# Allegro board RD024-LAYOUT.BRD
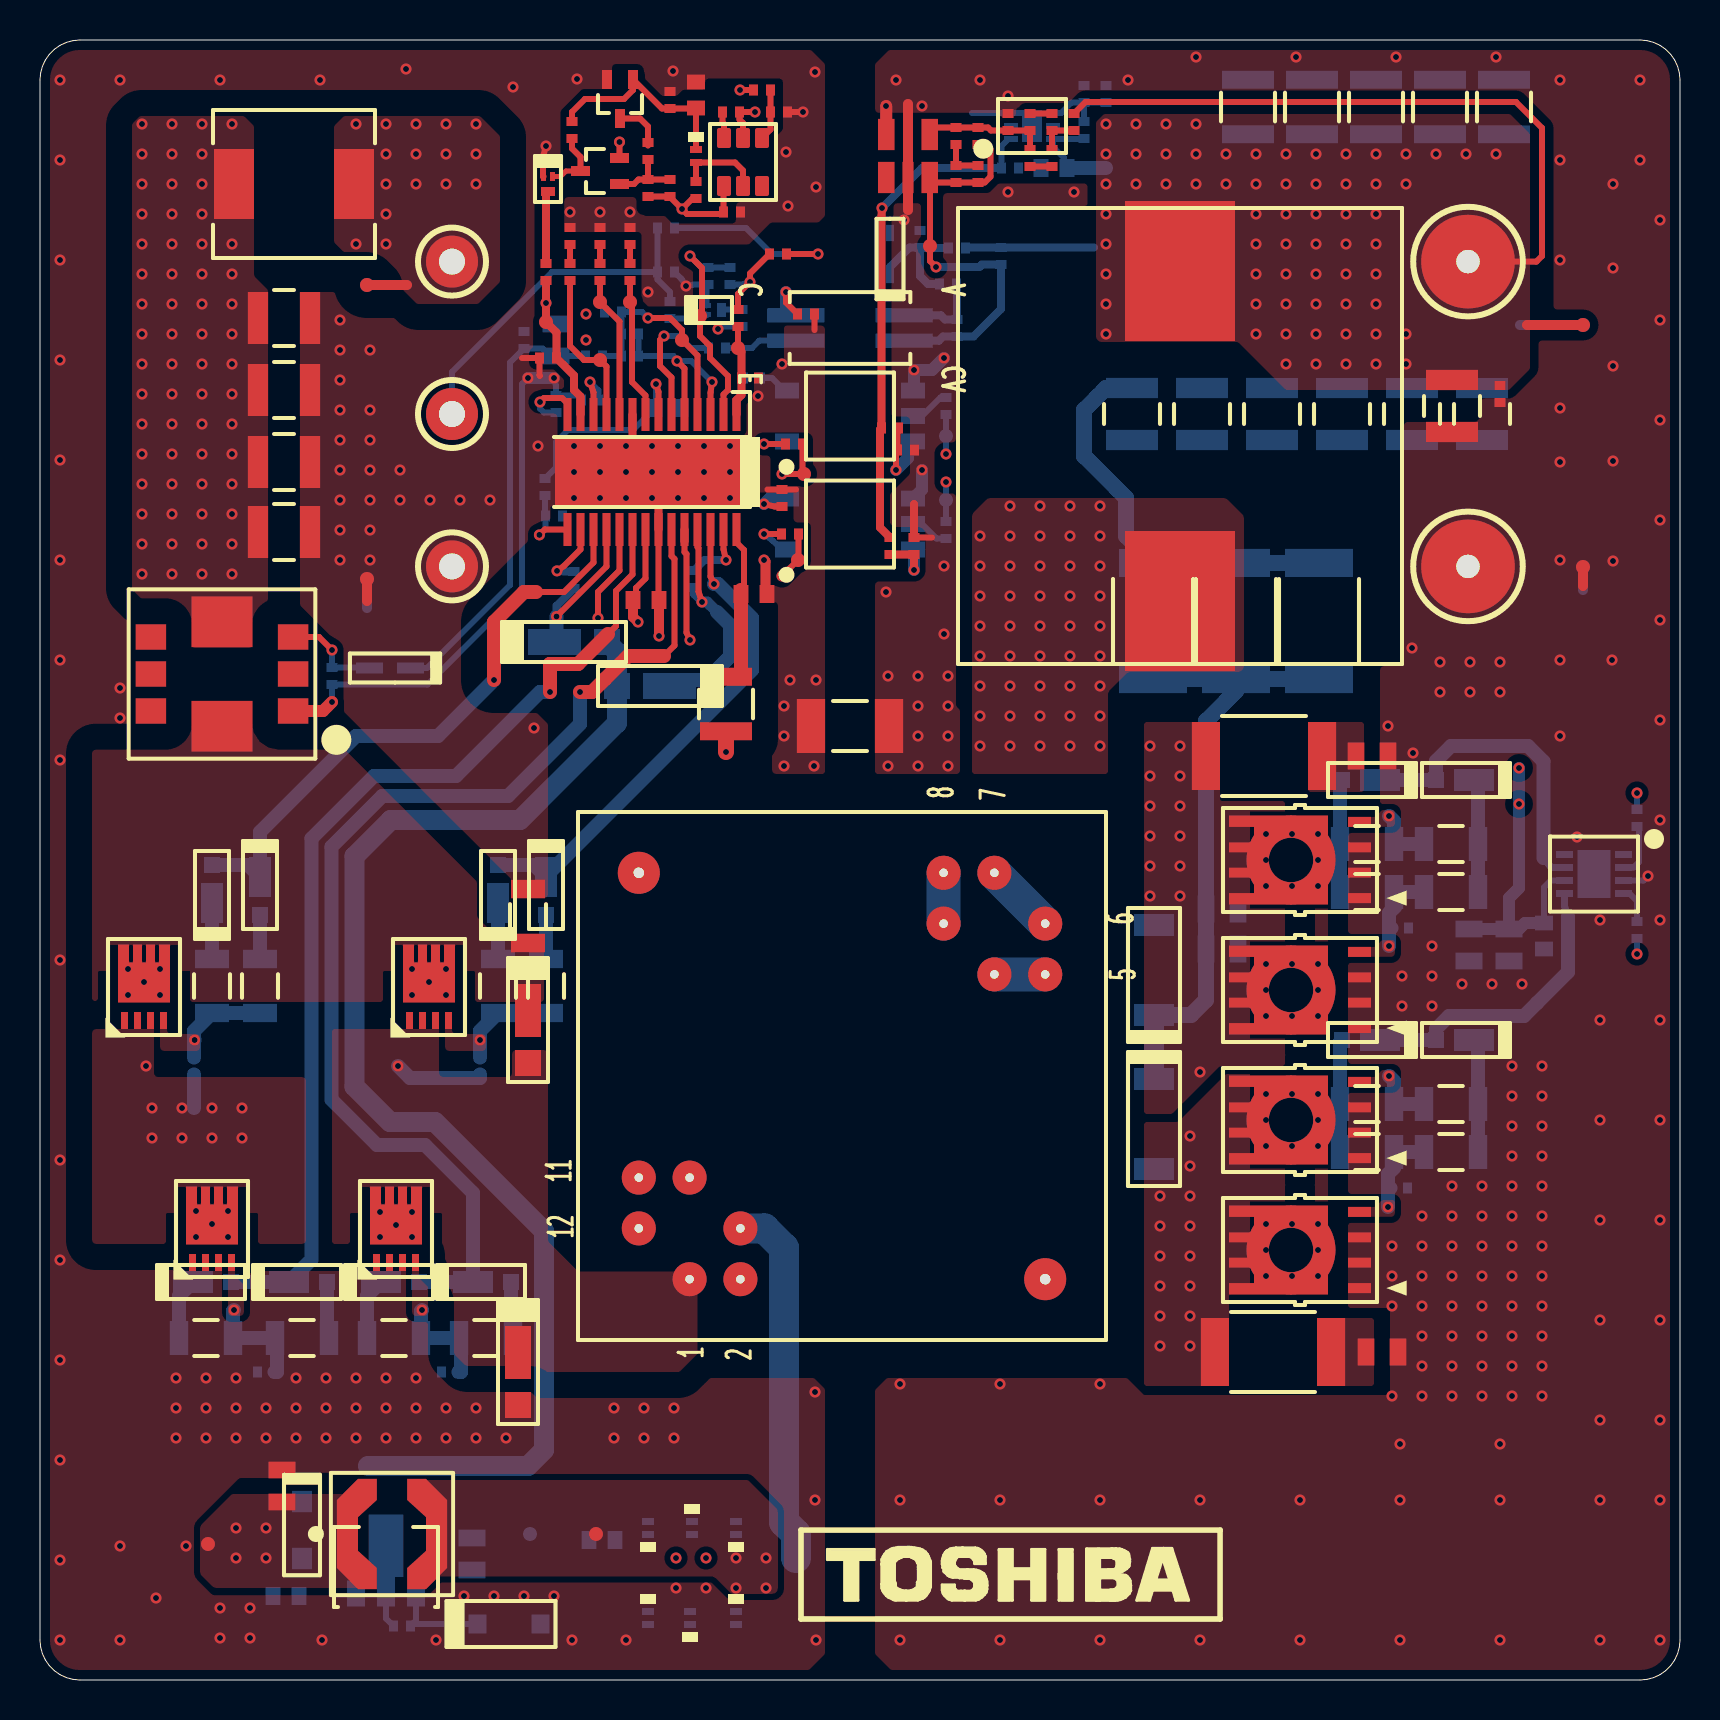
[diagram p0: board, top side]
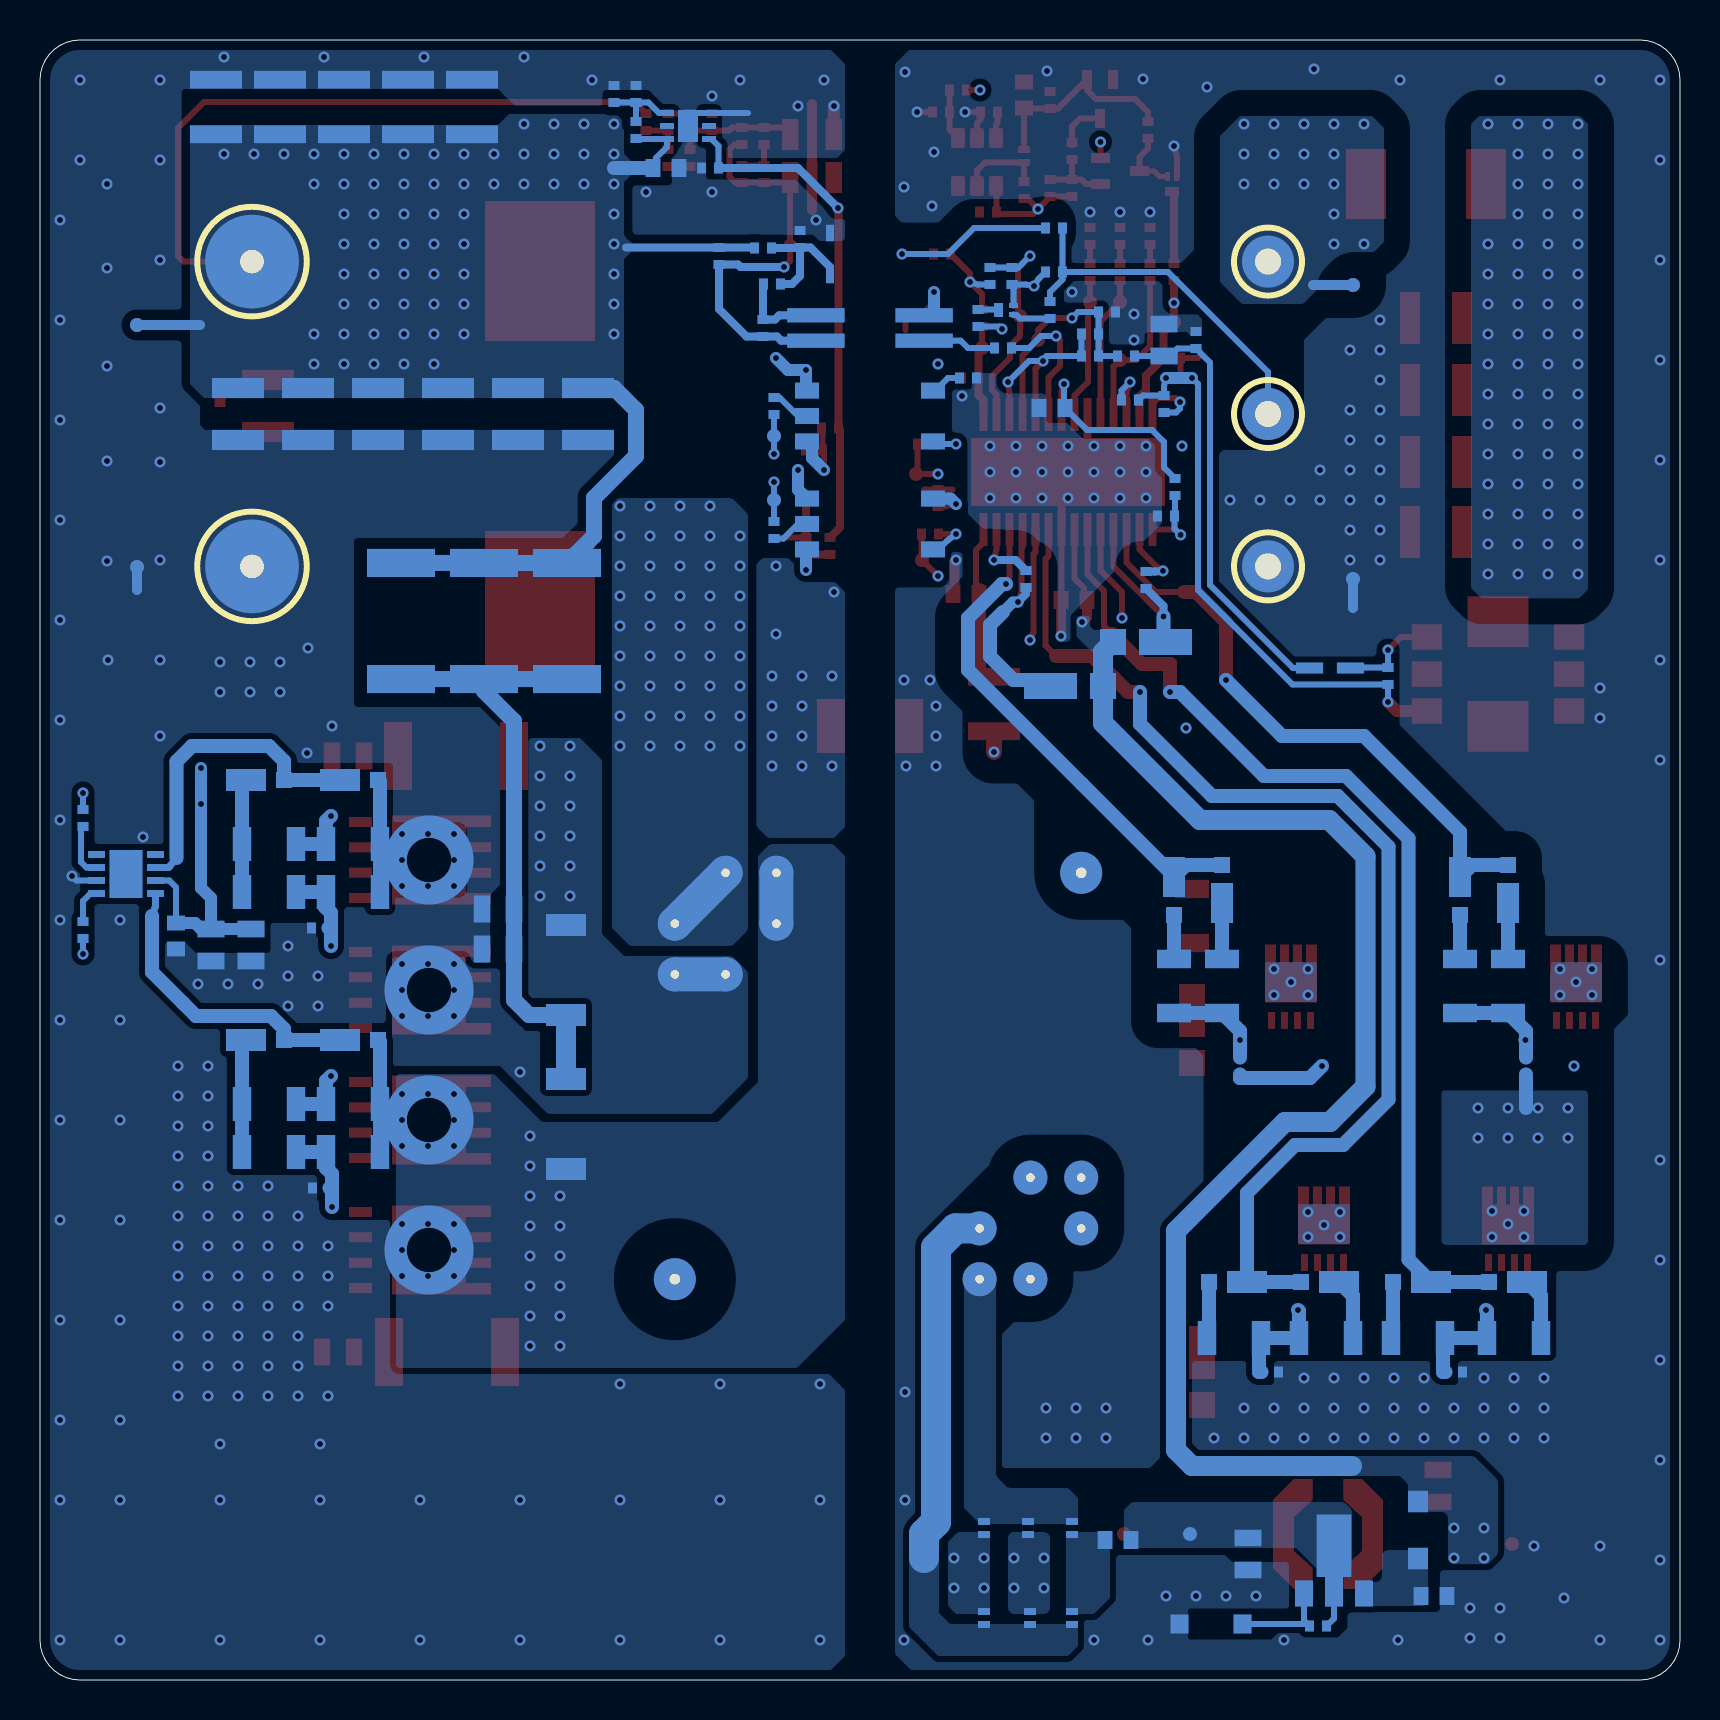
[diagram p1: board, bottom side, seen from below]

Outline 82 x 82 mm; copper layers: TOP, CONDUCTIVE2, CONDUCTIVE3, CONDUCTIVE4, CONDUCTIVE5, BOTTOM. Coordinates in mm from the lower left corner of the outline.
Outline path: 0,80 0.03,80.35 0.12,80.68 0.27,81 0.47,81.29 0.71,81.53 1,81.73 1.32,81.88 1.65,81.97 2,82 80,82 80.35,81.97 80.68,81.88 81,81.73 81.29,81.53 81.53,81.29 81.73,81 81.88,80.68 81.97,80.35 82,80 82,2 81.97,1.65 81.88,1.32 81.73,1 81.53,0.71 81.29,0.47 81,0.27 80.68,0.12 80.35,0.03 80,0 2,0 1.65,0.03 1.32,0.12 1,0.27 0.71,0.47 0.47,0.71 0.27,1 0.12,1.32 0.03,1.65 0,2 0,80

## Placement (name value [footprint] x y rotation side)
C1  -  [FTP_23]  12.2 57.4 180 top
C2  -  [FTP_23]  12.2 60.9 180 top
C3  -  [FTP_23]  12.2 64.5 180 top
C4  -  [FTP_23]  12.2 68.1 180 top
C5  -  [FTP_29]  32.7 55.05 270 bottom
C6  -  [FTP_21]  24.4 38.2 270 top
C7  -  [FTP_29]  26.7 55 270 bottom
C8  -  [FTP_19]  12.1 9.7 270 top
C9  -  [FTP_17]  12.3 4.2 0 bottom
C10  -  [FTP_19]  21.6 6.3 90 bottom
C11  -  [FTP_17]  50.7 75.6 0 bottom
C12  -  [FTP_29]  52.2 79.3 270 bottom
C13  -  [FTP_29]  48.5 75.6 180 bottom
C14  -  [FTP_17]  75.2 37.2 90 bottom
C15  -  [FTP_19]  73.45 36.75 90 bottom
C16  -  [FTP_19]  71.45 36.75 90 bottom
C17  -  [FTP_19]  66.6 46.2 180 top
C18  -  [FTP_19]  67.1 16.4 180 top
C19  -  [FTP_19]  59.1 38.55 180 bottom
C20  -  [FTP_29]  73 64.3 90 top
C21  -  [FTP_23]  70.6 63.7 90 top
C22  -  [FTP_23]  54.6 63.3 90 bottom
C23  -  [FTP_23]  58.1 63.3 90 bottom
C24  -  [FTP_23]  61.6 63.3 90 bottom
C25  -  [FTP_23]  68.6 63.3 90 bottom
C26  -  [FTP_23]  65.1 63.3 90 bottom
C27  -  [FTP_23]  72.1 63.3 90 bottom
C28  -  [FTP_17]  35.7 54.3 180 top
C29  -  [FTP_17]  30.3 54 180 top
C30  -  [FTP_29]  28.65 68.4 0 bottom
C31  -  [FTP_29]  34.6 73.4 180 top
C32  -  [FTP_29]  34.55 78.4 180 top
C33  -  [FTP_29]  25.4 66.1 0 top
C34  -  [FTP_29]  25.8 63.8 270 bottom
C35  -  [FTP_29]  27.5 64 0 bottom
C36  -  [FTP_29]  38.3 68.3 180 top
C37  -  [FTP_29]  46.9 75.3 270 top
C38  -  [FTP_29]  45.8 77.2 270 top
C39  -  [FTP_29]  50.6 77.9 90 top
C40  -  [FTP_29]  43.3 61.5 180 top
C41  -  [FTP_29]  43.7 56.7 270 top
C42  -  [FTP_25]  40.5 47.7 180 top
C43  -  [FTP_17]  32.8 79.25 270 top
C44  -  [FTP_29]  30.4 74.6 270 top
C45  -  [FTP_17]  31.4 63.6 180 bottom
C46  -  [FTP_29]  46.9 77.2 270 top
C47  -  [FTP_29]  35.5 65.1 180 top
C48  -  [FTP_29]  44 72.05 270 bottom
CAM9  -  [UTOS26]  38.05 3.05 0 top
CN1  -  [FTP_13]  20.6 70.92 0 top
CN2  -  [FTP_13]  20.6 55.68 0 top
CN3  -  [FTP_13]  20.6 63.3 0 top
CN4  -  [FTP_16]  71.4 70.92 270 top
CN5  -  [FTP_16]  71.4 55.68 270 top
D1  -  [FTP_1]  17.5 50.6 180 bottom
D2  -  [FTP_52]  30.5 49.7 180 bottom
D3  -  [FTP_94]  22.9 39.5 90 bottom
D4  -  [FTP_94]  25.3 39.5 270 bottom
D5  -  [FTP_94]  17.7 19.9 0 bottom
D6  -  [FTP_94]  22.3 19.9 0 bottom
D7  -  [FTP_52]  24.4 32.5 270 top
D8  -  [FTP_52]  23.9 15.4 270 top
D9  -  [FTP_52]  26.7 51.9 0 bottom
D10  -  [FTP_94]  8.6 39.5 90 bottom
D11  -  [FTP_94]  11 39.5 270 bottom
D12  -  [FTP_94]  8.3 19.9 0 bottom
D13  -  [FTP_94]  13.1 19.9 0 bottom
D14  -  [FTP_10]  55.7 35.5 90 bottom
D15  -  [FTP_10]  55.7 27.8 270 bottom
D16  -  [FTP_94]  71.05 45 180 bottom
D17  -  [FTP_94]  66.35 45 180 bottom
D18  -  [FTP_94]  71.05 32 180 bottom
D19  -  [FTP_94]  66.35 32 180 bottom
D20  -  [FTP_8]  13.1 7.5 270 bottom
D21  -  [FTP_75]  23.45 2.8 0 bottom
D22  -  [FTP_96]  34.8 3.1 270 bottom
D23  -  [FTP_96]  34.8 7.6 90 bottom
D24  -  [FTP_96]  30.4 3.1 270 bottom
D25  -  [FTP_96]  32.5 3.1 90 bottom
D26  -  [FTP_96]  32.6 7.6 270 bottom
D27  -  [FTP_96]  30.4 7.6 90 bottom
D28  -  [FTP_41]  42.5 71.3 270 bottom
D29  -  [FTP_96]  32.8 76.2 270 top
DP1  -  [FTP_88]  29.9 44.8 0 bottom
DP2  -  [FTP_88]  28.25 50.05 180 top
DP3  -  [FTP_88]  22.7 50.9 90 top
DP4  -  [FTP_88]  25.5 50.8 90 top
DP5  -  [FTP_88]  73.1 46.7 180 bottom
DP6  -  [FTP_88]  74.85 33.85 180 bottom
DP7  -  [FTP_88]  27.8 7.3 180 top
DP8  -  [FTP_88]  24.5 7.3 0 bottom
DP9  -  [FTP_88]  34.9 66.6 0 top
DP10  -  [FTP_88]  33 68.2 0 top
DP11  -  [FTP_88]  32.1 67 0 top
DP12  -  [FTP_88]  25.3 67.9 0 top
DP13  -  [FTP_88]  28 66 0 top
DP14  -  [FTP_88]  28 68.9 0 top
DP15  -  [FTP_88]  29.5 68.9 0 top
DP16  -  [FTP_88]  8.4 6.8 180 top
DP17  -  [FTP_88]  37.9 56 90 top
DP18  -  [FTP_88]  38.2 60.3 90 top
DP19  -  [FTP_88]  44.5 71.7 270 top
DP20  -  [FTP_88]  45.3 62.2 90 bottom
DP21  -  [FTP_88]  45.3 59 90 bottom
DP31  -  [FTP_88]  16.35 69.75 0 top
DP32  -  [FTP_88]  16.35 55.05 0 top
DP34  -  [FTP_88]  77.15 67.75 0 top
DP35  -  [FTP_88]  77.15 55.65 0 top
DP41  -  [FTP_88]  16.35 69.75 180 bottom
DP42  -  [FTP_88]  16.35 55.05 180 bottom
DP44  -  [FTP_88]  77.15 67.75 180 bottom
DP45  -  [FTP_88]  77.15 55.65 180 bottom
DS1  -  [FTP_90]  40.5 67.6 270 bottom
DS2  -  [FTP_3]  40.5 63.2 90 bottom
DS3  -  [FTP_3]  40.5 57.8 90 bottom
IC1  -  [FTP_47]  30.6 60.4 180 top
IC2  -  [FTP_84]  77.7 40.3 270 bottom
IC3  -  [FTP_86]  49.6 77.7 90 bottom
IC4  -  [FTP_77]  43.4 76.2 0 top
IC5  -  [FTP_79]  35.15 75.9 0 top
L1  -  [FTP_45]  12.7 74.8 180 top
L2  -  [FTP_14]  57 62.2 90 top
L3  -  [FTP_49]  17.6 7.3 0 top
Q1  -  [FTP_73]  19.45 34.65 0 top
Q2  -  [FTP_73]  17.8 22.55 0 top
Q3  -  [FTP_73]  5.2 34.65 0 top
Q4  -  [FTP_73]  8.6 22.55 0 top
Q5  -  [FTP_6]  63 41 90 top
Q6  -  [FTP_6]  63 34.5 90 top
Q7  -  [FTP_6]  63 28 90 top
Q8  -  [FTP_6]  63 21.5 90 top
Q9  -  [FTP_98]  33.7 68.5 0 bottom
Q10  -  [FTP_82]  17.3 6.1 180 bottom
Q11  -  [FTP_98]  25.4 74.8 270 top
Q12  -  [FTP_54]  29 79.05 180 top
Q13  -  [FTP_54]  28 75.45 90 top
R1  -  [FTP_29]  14.6 50.2 90 bottom
R2  -  [FTP_35]  22.9 34.7 270 bottom
R3  -  [FTP_35]  25.3 34.7 270 bottom
R4  -  [FTP_29]  22 30.7 90 bottom
R5  -  [FTP_35]  17.7 17.1 0 bottom
R6  -  [FTP_35]  22.3 17.1 180 bottom
R7  -  [FTP_29]  20.5 15.4 0 bottom
R8  -  [FTP_35]  8.6 34.7 270 bottom
R9  -  [FTP_35]  11 34.7 270 bottom
R10  -  [FTP_29]  7.7 30.7 90 bottom
R11  -  [FTP_35]  8.3 17.1 0 bottom
R12  -  [FTP_35]  13.1 17.1 180 bottom
R13  -  [FTP_29]  11.3 15.4 0 bottom
R14  -  [FTP_31]  28.1 7 0 bottom
R15  -  [FTP_29]  18.1 2.7 180 bottom
R16  -  [FTP_56#2]  63.95 52.95 90 bottom
R17  -  [FTP_56#2]  59.8 52.95 90 bottom
R18  -  [FTP_56#2]  55.65 52.95 90 bottom
R19  -  [FTP_29]  52.2 77.5 270 bottom
R20  -  [FTP_29]  53.3 79.3 270 bottom
R21  -  [FTP_29]  79.85 43.1 270 bottom
R22  -  [FTP_29]  79.85 37.5 90 bottom
R24  -  [FTP_35]  66.35 41.8 0 bottom
R25  -  [FTP_35]  70.55 41.8 180 bottom
R26  -  [FTP_35]  70.55 39.4 180 bottom
R27  -  [FTP_35]  66.35 39.4 0 bottom
R28  -  [FTP_29]  68 37.6 180 bottom
R29  -  [FTP_56]  61.2 46.2 180 top
R30  -  [FTP_35]  66.35 28.8 0 bottom
R31  -  [FTP_35]  70.55 28.8 180 bottom
R32  -  [FTP_35]  70.55 26.4 180 bottom
R33  -  [FTP_35]  66.35 26.4 0 bottom
R34  -  [FTP_29]  67.95 24.6 180 bottom
R35  -  [FTP_56]  61.65 16.4 180 top
R36  -  [FTP_33]  59.1 36.55 180 bottom
R37  -  [FTP_29]  31.3 72.6 0 bottom
R38  -  [FTP_29]  36.9 71.3 0 top
R39  -  [FTP_37]  34.3 48.8 90 top
R40  -  [FTP_29]  31.5 68.5 270 bottom
R41  -  [FTP_29]  31.3 70.4 180 bottom
R42  -  [FTP_29]  34.5 70.2 270 bottom
R43  -  [FTP_29]  33.4 70.2 90 bottom
R44  -  [FTP_29]  27.7 66.2 0 bottom
R45  -  [FTP_33]  25.8 67 270 bottom
R46  -  [FTP_29]  29.5 66.2 180 bottom
R47  -  [FTP_29]  36.1 79.5 180 top
R48  -  [FTP_29]  36.95 78.4 180 top
R49  -  [FTP_29]  32.8 74.5 270 top
R50  -  [FTP_29]  30.4 76.45 270 top
R51  -  [FTP_29]  29.5 70.4 270 top
R52  -  [FTP_29]  29.5 72.2 270 top
R53  -  [FTP_29]  28 72.2 270 top
R54  -  [FTP_29]  26.5 72.2 270 top
R55  -  [FTP_29]  25.3 70.4 270 top
R56  -  [FTP_29]  45.85 71.6 0 bottom
R57  -  [FTP_29]  48.05 71.2 90 bottom
R58  -  [FTP_29]  45.8 75.3 90 top
R59  -  [FTP_29]  51.7 77.9 90 top
R60  -  [FTP_29]  50.6 76.1 90 top
R61  -  [FTP_29]  49.5 76.1 270 top
R62  -  [FTP_29]  49.5 77.9 90 top
R63  -  [FTP_29]  48.4 77.9 270 top
R64  -  [FTP_29]  25.25 59.65 90 bottom
R65  -  [FTP_29]  25.7 58.2 180 bottom
R66  -  [FTP_29]  37.7 61.8 180 top
R67  -  [FTP_29]  35.6 65.1 0 bottom
R68  -  [FTP_29]  37.5 57.3 180 top
R69  -  [FTP_29]  37.1 59.1 270 top
R70  -  [FTP_29]  42.5 62.6 180 top
R71  -  [FTP_29]  45.3 63.7 270 bottom
R72  -  [FTP_29]  42.5 56.7 90 top
R73  -  [FTP_29]  45.3 57.5 90 bottom
R74  -  [FTP_29]  26.6 77.5 270 top
R75  -  [FTP_29]  31.5 74.6 270 top
R77  -  [FTP_29]  45.85 67.6 90 bottom
R78  -  [FTP_29]  45.4 69.8 180 bottom
R79  -  [FTP_29]  33.85 66.6 0 bottom
R80  -  [FTP_29]  34.9 68.1 270 top
R87  -  [FTP_29]  31.5 79 270 top
R88  -  [FTP_29]  24.2 67 270 bottom
R89  -  [FTP_29]  28 70.4 270 top
R90  -  [FTP_29]  26.5 70.4 270 top
R91  -  [FTP_29]  29.5 67.3 180 bottom
R92  -  [FTP_37]  73.2 78.65 270 bottom
R93  -  [FTP_37]  70 78.65 270 bottom
R94  -  [FTP_37]  66.8 78.65 270 bottom
R95  -  [FTP_37]  63.6 78.65 270 bottom
R96  -  [FTP_37]  60.4 78.65 270 bottom
R97  -  [FTP_29]  35.1 68.1 270 bottom
T1  -  [FTP_12]  9.1 50.3 90 top
T2  -  [FTP_15]  40.1 30.2 90 top

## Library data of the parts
C1-C4 = PRT_2: alternate symbols: (T:FTP_23;B:FTP_24)
C5 C7 C12 C20 C31 C32 C34 C36 C40 C41 C44 C46 C48 = PRT_4: alternate symbols: (T:FTP_29;B:FTP_30)
C6 = PRT_13: alternate symbols: (T:FTP_21;B:FTP_22)
C8 = PRT_39: alternate symbols: (T:FTP_19;B:FTP_20)
C9 C11 C14 C29 C45 = PRT_34: alternate symbols: (T:FTP_17;B:FTP_18)
C10 = PRT_33: alternate symbols: (T:FTP_19;B:FTP_20)
C13 = PRT_76: alternate symbols: (T:FTP_29;B:FTP_30)
C15 C16 = PRT_75: alternate symbols: (T:FTP_19;B:FTP_20)
C17 C18 = PRT_85: alternate symbols: (T:FTP_19;B:FTP_20)
C19 = PRT_77: alternate symbols: (T:FTP_19;B:FTP_20)
C21-C27 = PRT_74: alternate symbols: (T:FTP_23;B:FTP_24)
C28 = PRT_51: alternate symbols: (T:FTP_17;B:FTP_18)
C30 C37 = PRT_55: alternate symbols: (T:FTP_29;B:FTP_30)
C33 = PRT_20: alternate symbols: (T:FTP_29;B:FTP_30)
C35 = PRT_19: alternate symbols: (T:FTP_29;B:FTP_30)
C38 C39 = PRT_23: alternate symbols: (T:FTP_29;B:FTP_30)
C42 = PRT_22: alternate symbols: (T:FTP_25;B:FTP_26)
C43 = PRT_5: alternate symbols: (T:FTP_17;B:FTP_18)
C47 = PRT_50: alternate symbols: (T:FTP_29;B:FTP_30)
CAM9 = PRT_89: alternate symbols: (FTP_100)
CN1-CN3 = PRT_16: alternate symbols: (T:FTP_13;B:FTP_13_B,FTP_13)
CN4 CN5 = PRT_86: alternate symbols: (T:FTP_16;B:FTP_16_B,FTP_16)
D1 = PRT_3: alternate symbols: (T:FTP_1;B:FTP_2)
D2 D7-D9 = PRT_9: alternate symbols: (T:FTP_52;B:FTP_53)
D3-D6 D10-D13 D16-D19 = PRT_7: alternate symbols: (T:FTP_94;B:FTP_95)
D14 D15 = PRT_38: alternate symbols: (T:FTP_10;B:FTP_11)
D20 = PRT_49: alternate symbols: (T:FTP_8;B:FTP_9)
D21 = PRT_35: alternate symbols: (T:FTP_75;B:FTP_76)
D22-D27 D29 = PRT_48: alternate symbols: (T:FTP_96;B:FTP_97)
D28 = PRT_63: alternate symbols: (T:FTP_41;B:FTP_42)
DP1-DP21 DP31 DP32 DP34 DP35 DP41 DP42 DP44 DP45 = PRT_10: alternate symbols: (T:FTP_88;B:FTP_89)
DS1 = PRT_21: alternate symbols: (T:FTP_90;B:FTP_91)
DS2 DS3 = PRT_72: alternate symbols: (T:FTP_3;B:FTP_4)
IC1 = PRT_6: alternate symbols: (T:FTP_47;B:FTP_47_B,FTP_47)
IC2 = PRT_87: alternate symbols: (T:FTP_84;B:FTP_85)
IC3 = PRT_78: alternate symbols: (T:FTP_86;B:FTP_87)
IC4 = PRT_56: alternate symbols: (T:FTP_77;B:FTP_78)
IC5 = PRT_58: alternate symbols: (T:FTP_79;B:FTP_80)
L1 = PRT_1: alternate symbols: (T:FTP_45;B:FTP_45_B,FTP_45)
L2 = PRT_73: alternate symbols: (T:FTP_14;B:FTP_14_B,FTP_14)
L3 = PRT_37: alternate symbols: (T:FTP_49;B:FTP_50)
Q1-Q4 = PRT_15: alternate symbols: (T:FTP_73,FTP_61,FTP_62,FTP_63,FTP_69,FTP_64,FTP_70;B:FTP_74,FTP_65,FTP_66,FTP_67,FTP_71,FTP_68,FTP_72)
Q5-Q8 = PRT_88: alternate symbols: (T:FTP_6;B:FTP_7)
Q9 Q11 = PRT_18: alternate symbols: (T:FTP_98;B:FTP_99)
Q10 = PRT_36: alternate symbols: (T:FTP_82;B:FTP_83)
Q12 = PRT_62: alternate symbols: (T:FTP_54;B:FTP_55)
Q13 = PRT_61: alternate symbols: (T:FTP_54;B:FTP_55)
R1 R4 R7 R10 R13 R28 R34 R49 R50 R57 R74 R75 R87 R90 = PRT_8: alternate symbols: (T:FTP_29;B:FTP_30)
R2 R5 = PRT_14: alternate symbols: (T:FTP_35;B:FTP_36)
R3 R6 R8 R9 R11 R12 R24-R27 R30-R33 = PRT_12: alternate symbols: (T:FTP_35;B:FTP_36)
R14 = PRT_41: alternate symbols: (T:FTP_31;B:FTP_32)
R15 = PRT_40: alternate symbols: (T:FTP_29;B:FTP_30)
R16-R18 = PRT_84: alternate symbols: (T:FTP_56;B:FTP_57)
R19 = PRT_81: alternate symbols: (T:FTP_29;B:FTP_30)
R20 = PRT_82: alternate symbols: (T:FTP_29;B:FTP_30)
R21 R22 R44 R55 R97 = PRT_30: alternate symbols: (T:FTP_29;B:FTP_30)
R29 R35 = PRT_83: alternate symbols: (T:FTP_56;B:FTP_57)
R36 = PRT_80: alternate symbols: (T:FTP_33;B:FTP_34)
R37 = PRT_29: alternate symbols: (T:FTP_29;B:FTP_30)
R38 R40 = PRT_27: alternate symbols: (T:FTP_29;B:FTP_30)
R39 = PRT_31: alternate symbols: (T:FTP_37;B:FTP_38)
R41 = PRT_26: alternate symbols: (T:FTP_29;B:FTP_30)
R42 = PRT_59: alternate symbols: (T:FTP_29;B:FTP_30)
R43 = PRT_28: alternate symbols: (T:FTP_29;B:FTP_30)
R45 = PRT_57: alternate symbols: (T:FTP_33;B:FTP_34)
R46 = PRT_66: alternate symbols: (T:FTP_29;B:FTP_30)
R47 = PRT_53: alternate symbols: (T:FTP_29;B:FTP_30)
R48 = PRT_54: alternate symbols: (T:FTP_29;B:FTP_30)
R51 = PRT_65: alternate symbols: (T:FTP_29;B:FTP_30)
R52 R64 R65 R70-R73 R91 = PRT_25: alternate symbols: (T:FTP_29;B:FTP_30)
R53 R54 = PRT_52: alternate symbols: (T:FTP_29;B:FTP_30)
R56 = PRT_71: alternate symbols: (T:FTP_29;B:FTP_30)
R58 = PRT_70: alternate symbols: (T:FTP_29;B:FTP_30)
R59 = PRT_24: alternate symbols: (T:FTP_29;B:FTP_30)
R60 = PRT_42: alternate symbols: (T:FTP_29;B:FTP_30)
R61 = PRT_43: alternate symbols: (T:FTP_29;B:FTP_30)
R62 = PRT_60: alternate symbols: (T:FTP_29;B:FTP_30)
R63 = PRT_44: alternate symbols: (T:FTP_29;B:FTP_30)
R66 R68 = PRT_45: alternate symbols: (T:FTP_29;B:FTP_30)
R67 R69 = PRT_46: alternate symbols: (T:FTP_29;B:FTP_30)
R77 = PRT_68: alternate symbols: (T:FTP_29;B:FTP_30)
R78 = PRT_69: alternate symbols: (T:FTP_29;B:FTP_30)
R79 = PRT_67: alternate symbols: (T:FTP_29;B:FTP_30)
R80 = PRT_32: alternate symbols: (T:FTP_29;B:FTP_30)
R88 = PRT_47: alternate symbols: (T:FTP_29;B:FTP_30)
R89 = PRT_64: alternate symbols: (T:FTP_29;B:FTP_30)
R92-R96 = PRT_79: alternate symbols: (T:FTP_37;B:FTP_38)
T1 = PRT_11: alternate symbols: (T:FTP_12;B:FTP_12_B,FTP_12)
T2 = PRT_17: alternate symbols: (T:FTP_15;B:FTP_15_B,FTP_15)

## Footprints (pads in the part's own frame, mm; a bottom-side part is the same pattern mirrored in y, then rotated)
FTP_1
  rect 1.36x0.55 smd: A(1.025,0) C(-1.025,0)
FTP_3
  rect 0.8x1.2 smd: 1(-1.27,-3.15) 3(1.27,-3.15) 4(1.27,3.15) 5(0,3.15) 6(-1.27,3.15)
FTP_6
  rect 4.45x3.7 smd: (0,0.45)
  rect 0.5x1.15 smd: 1(-1.905,-2.975) 2(-0.635,-2.975) 3(0.635,-2.975) 4(1.905,-2.975)
  rect 0.57x1.25 smd: 5(1.94,2.925) 8(-1.94,2.925)
  rect 0.5x1.25 smd: 6(0.635,2.925) 7(-0.635,2.925)
FTP_8
  rect 1.074x1 smd: A(1.425,0) C(-1.425,0)
FTP_10
  rect 1.1x2 smd: A(2.25,0) C(-2.25,0)
FTP_12
  rect 1.27x1.52 smd: 1(-1.85,-3.555) 2(0,-3.555) 3(1.85,-3.555) 4(1.85,3.555) 5(0,3.555) 6(-1.85,3.555)
  rect 2.54x3.05 smd: 7(2.615,0) 8(-2.615,0)
FTP_13
  round 2.6 hole 1.3: 1(0,0)
FTP_14
  rect 7x5.5 smd: 1(-8.25,0) 2(8.25,0)
FTP_15
  custom 0.425x0.425 hole 1: 1(-10.16,7.62) 2(-10.16,5.08) 3(-7.62,5.08) 4(5.08,-7.62) 5(5.08,-10.16) 6(7.62,-10.16) 7(10.16,-7.62) 8(10.16,-5.08) 9(7.62,-5.08) 10(-5.08,7.62) 11(-5.08,10.16) 12(-7.62,10.16)
  custom 0.525x0.525 hole 1.25: 13(-10.16,-10.16) 14(10.16,10.16)
FTP_16
  custom 1.17x1.17 hole 2.34: 1(0,0)
FTP_17
  rect 0.74x0.9 smd: 1(-0.65,0) 2(0.65,0)
FTP_19
  rect 0.83x1.35 smd: 1(-0.8,0) 2(0.8,0)
FTP_21
  rect 0.92x1.7 smd: 1(-1.35,0) 2(1.35,0)
FTP_23
  rect 1.01x2.6 smd: 1(-1.3,0) 2(1.3,0)
FTP_25
  rect 1.41x2.7 smd: 1(-1.95,0) 2(1.95,0)
FTP_29
  rect 0.45x0.55 smd: 1(-0.425,0) 2(0.425,0)
FTP_31
  rect 0.74x0.9 smd: 1(-0.65,0) 2(0.65,0)
FTP_33
  rect 0.83x1.35 smd: 1(-0.8,0) 2(0.8,0)
FTP_35
  rect 0.92x1.7 smd: 1(-1.35,0) 2(1.35,0)
FTP_37
  rect 0.895x2.6 smd: 1(-1.363,0) 2(1.363,0)
FTP_41
  rect 0.824x0.4 smd: A(-1.05,0) C(1.05,0)
FTP_45
  rect 2x3.5 smd: 1(-3,0) 2(3,0)
FTP_47
  rect 0.4x1.65 smd: 1(-4.225,-2.875) 2(-3.575,-2.875) 3(-2.925,-2.875) 4(-2.275,-2.875) 5(-1.625,-2.875) 6(-0.975,-2.875) 7(-0.325,-2.875) 8(0.325,-2.875) 9(0.975,-2.875) 10(1.625,-2.875) 11(2.275,-2.875) 12(2.925,-2.875) 13(3.575,-2.875) 14(4.225,-2.875) 15(4.225,2.875) 16(3.575,2.875) 17(2.925,2.875) 18(2.275,2.875) 19(1.625,2.875) 20(0.975,2.875) 21(0.325,2.875) 22(-0.325,2.875) 23(-0.975,2.875) 24(-1.625,2.875) 25(-2.275,2.875) 26(-2.925,2.875) 27(-3.575,2.875) 28(-4.225,2.875)
  custom 0.85x0.85 smd: 29(0,0)
FTP_49
  rect 0.5x0.5 smd: 1(-2.3,0) 2(2.3,0)
FTP_52
  rect 1.3x1.3 smd: A(1.65,0)
  rect 2.65x1.3 smd: C(-0.975,0)
FTP_54
  rect 0.5x0.95 smd: B(-0.65,-0.975) C(0,0.975) E(0.65,-0.975)
FTP_56
  rect 1.405x3.4 smd: 1(-2.902,0) 2(2.902,0)
FTP_56#2
  rect 1.405x3.4 smd: 1(2.902,0) 2(-2.902,0)
FTP_73
  rect 0.35x0.85 smd: 1(-0.975,-1.675) 2(-0.325,-1.675) 3(0.325,-1.675) 4(0.975,-1.675)
  custom 0.65x0.65 smd: 5(0,0.675)
FTP_75
  rect 0.9x0.95 smd: A(1.575,0) C(-1.575,0)
FTP_77
  rect 0.825x1.56 smd: 1(-1.087,-1.075) 3(1.087,-1.075) 4(1.087,1.075) 5(-1.087,1.075)
  rect 0.55x1.56 smd: 2(0,-1.075)
FTP_79
  custom 0.175x0.175 smd: 1(-0.95,-1.2) 2(0,-1.2) 3(0.95,-1.2) 4(0.95,1.2) 5(0,1.2) 6(-0.95,1.2)
FTP_82
  rect 0.9x1.3 smd: B(-1.5,-1.775) E(1.5,-1.775)
  custom 0.433x0.433 smd: C(0,-0.125)
FTP_84
  rect 0.35x0.85 smd: 1(-0.975,-1.475) 2(-0.325,-1.475) 3(0.325,-1.475) 4(0.975,-1.475) 5(0.975,1.475) 6(0.325,1.475) 7(-0.325,1.475) 8(-0.975,1.475)
  rect 2.4x1.65 smd: 9(0,0)
FTP_86
  rect 0.3x0.7 smd: 1(-0.65,-1.05) 2(0,-1.05) 3(0.65,-1.05) 4(0.65,1.05) 5(0,1.05) 6(-0.65,1.05)
  rect 1.6x1 smd: 7(0,0)
FTP_88
  round 0.7 smd: 1(0,0)
FTP_90
  rect 0.711x2.87 smd: A(-0.635,-2.705) C(-0.635,2.705) CA(0.635,-2.705) E(0.635,2.705)
FTP_94
  rect 0.8x0.8 smd: A(1.25,0)
  rect 2x1.1 smd: C(-0.65,0)
FTP_96
  rect 0.35x0.6 smd: A(0.325,0) C(-0.325,0)
FTP_98
  rect 0.45x0.7 smd: D(0.375,0)
  rect 0.45x0.25 smd: G(-0.375,0.225) S(-0.375,-0.225)

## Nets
3V3_SEC: C13.2(TP-1) IC3.1 R70.2(TP-1) R72.2(TP-1)
12VOUT: C11.2(TP-1) C14.2(TP-1) C15.2(TP-1) C16.2(TP-1) C20.2(TP-1) C21.2(TP-1) C22.2(TP-1) C23.2(TP-1) C24.2(TP-1) C25.2(TP-1) C26.2(TP-1) C27.2(TP-1) CN4.1 DP34.1 DP44.1 IC2.6 IC3.6 L2.2(TP-1) R16.1(TP-1) R17.1(TP-1) R18.1(TP-1) R19.2(TP-1) R56.2(TP-1) R57.2(TP-1) R59.2(TP-1) R92.2(TP-1) R93.2(TP-1) R94.2(TP-1) R95.2(TP-1) R96.2(TP-1)
VIN: C1.2(TP-1) C2.2(TP-1) C3.2(TP-1) C4.2(TP-1) L1.2(TP-1) R37.2(TP-1) R38.2(TP-1) R39.1(TP-1) T1.7
$BN000001: Q9.D R97.1(TP-1)
$BN000002: C48.2(TP-1) D28.C R56.1(TP-1) R78.2(TP-1)
$BN000003: C44.1(TP-1) Q13.B R50.2(TP-1) R75.1(TP-1)
$BN000004: Q12.C R50.1(TP-1)
$BN000005: DS1.E R79.2(TP-1)
AUX_1: D23.A D26.C D27.A T2.2
AUX_2: D22.A D24.A D25.C T2.3
CS: D1.C R44.1(TP-1) R45.2(TP-1) R88.2(TP-1)
DC_IN: CN1.1 DP31.1 DP41.1 L1.1(TP-1)
ENABLE: CN3.1 R37.1(TP-1) R40.1(TP-1) R41.2(TP-1)
LGND: C11.1(TP-1) C12.1(TP-1) C13.1(TP-1) C14.1(TP-1) C15.1(TP-1) C16.1(TP-1) C17.1(TP-1) C18.1(TP-1) C19.1(TP-1) C20.1(TP-1) C21.1(TP-1) C22.1(TP-1) C23.1(TP-1) C24.1(TP-1) C25.1(TP-1) C26.1(TP-1) C27.1(TP-1) C40.1(TP-1) C41.1(TP-1) C42.1(TP-1) C48.1(TP-1) CN5.1 D28.A DP35.1 DP45.1 DS2.4 DS3.4 IC2.3 IC3.3 IC3.7 IC4.2 IC4.5 Q5.1 Q5.2 Q5.3 Q6.1 Q6.2 Q6.3 Q7.1 Q7.2 Q7.3 Q8.1 Q8.2 Q8.3 R20.1(TP-1) R28.1(TP-1) R34.1(TP-1) R36.1(TP-1) R63.1(TP-1) R92.1(TP-1) R93.1(TP-1) R94.1(TP-1) R95.1(TP-1) R96.1(TP-1)
LM5046REF: C31.2(TP-1) C36.2(TP-1) C44.2(TP-1) C45.2(TP-1) DS1.C IC1.7 IC5.1 Q13.E R49.2(TP-1) R64.2(TP-1) R75.2(TP-1)
LM5046VCC: C8.2(TP-1) C29.2(TP-1) D2.A D9.A D20.C DP16.1 IC1.21 L3.1(TP-1) R47.2(TP-1)
OUTB1: DP20.1 R21.1(TP-1) R71.2(TP-1)
OUTB2: DP21.1 R22.1(TP-1) R73.2(TP-1)
PN: C1.1(TP-1) C2.1(TP-1) C3.1(TP-1) C4.1(TP-1) C6.1(TP-1) C8.1(TP-1) C9.1(TP-1) C10.1(TP-1) C28.1(TP-1) C29.1(TP-1) C30.1(TP-1) C31.1(TP-1) C32.1(TP-1) C33.1(TP-1) C34.1(TP-1) C35.1(TP-1) C36.1(TP-1) C42.2(TP-1) C43.1(TP-1) C45.1(TP-1) C47.1(TP-1) CN2.1 D8.A D21.A D25.A D26.A DP32.1 DP42.1 IC1.9 IC1.22 IC1.29 IC5.5 Q2.1 Q2.2 Q2.3 Q4.1 Q4.2 Q4.3 Q9.S Q11.S Q12.E R1.1(TP-1) R7.1(TP-1) R13.1(TP-1) R41.1(TP-1) R43.1(TP-1) R45.1(TP-1) R48.1(TP-1) R52.1(TP-1) R53.1(TP-1) R54.1(TP-1) R65.1(TP-1) R67.1(TP-1) R69.1(TP-1) R87.1(TP-1) R88.1(TP-1) T1.1
SEC_1: D15.A Q7.5 Q7.6 Q7.7 Q7.8 Q8.5 Q8.6 Q8.7 Q8.8 R35.2(TP-1) T2.8 T2.9
SEC_2: L2.1(TP-1) T2.6 T2.7
SEC_3: D14.A Q5.5 Q5.6 Q5.7 Q5.8 Q6.5 Q6.6 Q6.7 Q6.8 R29.2(TP-1) T2.4 T2.5
SIG7: D3.A D4.C DP1.1 IC1.26
SIG8: C5.2(TP-1) D2.C IC1.25
SIG9: Q1.4 R2.2(TP-1) R3.2(TP-1) R4.2(TP-1)
SIG12: Q2.4 R5.2(TP-1) R6.2(TP-1) R7.2(TP-1)
SIG14: C7.2(TP-1) D9.C IC1.18
SIG16: Q4.4 R11.2(TP-1) R12.2(TP-1) R13.2(TP-1)
SIG17: Q3.4 R8.2(TP-1) R9.2(TP-1) R10.2(TP-1)
SIG18: D12.A D13.C DP4.1 IC1.20
SIG22: C6.2(TP-1) D7.C Q1.5 Q3.5 T1.8
SIG23: D1.A R1.2(TP-1) T1.3
SIG25: Q9.G R40.2(TP-1)
SIG27: DP10.1 IC1.2 R42.1(TP-1) R43.2(TP-1)
SIG28: IC2.4 R22.2(TP-1)
SIG29: IC2.2 R21.2(TP-1)
SIG37: C17.2(TP-1) R29.1(TP-1)
SIG39: C18.2(TP-1) R35.1(TP-1)
SIG41: C19.2(TP-1) D14.C D15.C R16.2(TP-1) R17.2(TP-1) R18.2(TP-1) R36.2(TP-1)
SIG43: C12.2(TP-1) IC3.4 R19.1(TP-1) R20.2(TP-1)
SIG49: IC1.3 IC1.5 R46.1(TP-1) R91.1(TP-1)
SIG52: DP14.1 IC1.10 R89.2(TP-1)
SIG53: DP13.1 IC1.11 R90.2(TP-1)
SIG54: DP18.1 IC1.24 R66.1(TP-1)
SIG55: DP17.1 IC1.19 R68.1(TP-1)
SIG63: C28.2(TP-1) IC1.28 R39.2(TP-1)
SIG64: C30.2(TP-1) DP11.1 IC1.4 R44.2(TP-1) R46.2(TP-1) R91.2(TP-1)
SIG66: C35.2(TP-1) IC1.12
SIG67: C33.2(TP-1) DP12.1 IC1.13 R55.2(TP-1) R97.2(TP-1)
SIG74: IC1.6 R79.1(TP-1)
SIG75: D3.C R2.1(TP-1)
SIG76: D4.A R3.1(TP-1)
SIG77: D5.C R5.1(TP-1)
SIG78: D5.A D6.C DP2.1 IC1.23
SIG79: D6.A R6.1(TP-1)
SIG80: D10.C R8.1(TP-1)
SIG81: D10.A D11.C DP3.1 IC1.17
SIG82: D11.A R9.1(TP-1)
SIG83: D12.C R11.1(TP-1)
SIG84: D13.A R12.1(TP-1)
SIG85: Q8.4 R32.2(TP-1) R33.2(TP-1) R34.2(TP-1)
SIG86: D16.A D17.C DP5.1 IC2.7
SIG87: Q6.4 R26.2(TP-1) R27.2(TP-1) R28.2(TP-1)
SIG89: D16.C R25.1(TP-1) R26.1(TP-1)
SIG90: Q5.4 R24.2(TP-1) R25.2(TP-1)
SIG91: D17.A R24.1(TP-1) R27.1(TP-1)
SIG92: D18.A D19.C DP6.1 IC2.5
SIG93: Q7.4 R30.2(TP-1) R31.2(TP-1)
SIG94: D19.A R30.1(TP-1) R33.1(TP-1)
SIG95: D18.C R31.1(TP-1) R32.1(TP-1)
SIG97: DS2.1 R66.2(TP-1)
SIG98: DS2.3 R67.2(TP-1)
SIG99: DS3.1 R68.2(TP-1)
SIG100: DS3.3 R69.2(TP-1)
SIG106: C40.2(TP-1) DS2.6 R70.1(TP-1)
SIG107: DS2.5 R71.1(TP-1)
SIG108: C41.2(TP-1) DS3.6 R72.1(TP-1)
SIG109: DS3.5 R73.1(TP-1)
SIG112: C34.2(TP-1) IC1.14
SIG122: C37.2(TP-1) C46.2(TP-1) DP19.1 DS1.CA IC4.3 R57.1(TP-1) R58.1(TP-1) R77.1(TP-1)
SIG124: C37.1(TP-1) C38.2(TP-1) R58.2(TP-1)
SIG126: R51.1(TP-1) R52.2(TP-1)
SIG127: DP15.1 IC1.8 R51.2(TP-1)
SIG129: DS1.A R77.2(TP-1) R78.1(TP-1)
SIG130: R60.1(TP-1) R61.2(TP-1)
SIG131: C39.2(TP-1) R62.2(TP-1)
SIG132: C39.1(TP-1) R59.1(TP-1) R60.2(TP-1)
SIG133: IC1.15 R64.1(TP-1) R65.2(TP-1)
SIG145: C5.1(TP-1) D7.A D8.C IC1.27 Q1.1 Q1.2 Q1.3 Q2.5 R4.1(TP-1) T2.1
SIG148: C7.1(TP-1) IC1.16 Q3.1 Q3.2 Q3.3 Q4.5 R10.1(TP-1) T2.11 T2.12
SIG151: Q11.D R55.1(TP-1)
SIG153: Q11.G Q13.C R74.2(TP-1)
SIG155: C32.2(TP-1) IC5.6
SIG156: IC5.4 R47.1(TP-1) R48.2(TP-1)
SIG158: C47.2(TP-1) DP9.1 IC1.1 R80.2(TP-1)
SIG161: C10.2(TP-1) DP8.1 Q10.C R14.1(TP-1) R15.2(TP-1)
SIG162: D22.C D23.C DP7.1 L3.2(TP-1)
SIG164: D21.C Q10.B R15.1(TP-1)
SIG165: D24.C D27.C R14.2(TP-1)
SIG168: C9.2(TP-1) D20.A Q10.E
SIG170: D29.A IC5.2 R49.1(TP-1)
SIG172: C43.2(TP-1) D29.C Q12.B R74.1(TP-1) R87.2(TP-1)
SIG173: R53.2(TP-1) R89.1(TP-1)
SIG174: R54.2(TP-1) R90.1(TP-1)
SIG176: R38.1(TP-1) R42.2(TP-1) R80.1(TP-1)
SIG178: C38.1(TP-1) C46.1(TP-1) IC4.4 R61.1(TP-1) R62.1(TP-1) R63.2(TP-1)

Pads without a net: IC2 1 8 9; IC3 2 5; IC4 1; IC5 3; T1 2 4 5 6; T2 10 13 14

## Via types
v1: diameter 0.55, hole 0.3, TOP to BOTTOM, 652 vias
v2: diameter 4.45, hole 2.225, TOP to BOTTOM, 4 vias

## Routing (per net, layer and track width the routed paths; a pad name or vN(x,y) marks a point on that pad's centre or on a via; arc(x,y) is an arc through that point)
3V3_SEC: length 25.2
  TOP w0.4: R72.2 42,57.62 42,62.52 R70.2 42.08,73.19 v1(42.1,73.6)
  BOTTOM w0.3: IC3.1 48.42,77.05 48.08,76.7 C13.2
  BOTTOM w0.4: C13.2 44.1,75.6 v1(42.1,73.6)
12VOUT: length 113.2
  TOP w0.3: R59.2 52.27,78.9 73.8,78.9 75.1,77.6 75.1,71.2 74.82,70.92 CN4.1
  TOP w0.5: DP34.1 74.35,67.75
  CONDUCTIVE3 w1: v1(73.95,43.8) v1(73.95,45.6) 71.45,45.6 65.8,51.25 65.8,64.8
  BOTTOM w0.3: C14.2 75.2,39.64 75.54,39.98 76.22,39.98 ; C11.2 51.2,75.75 51.2,76.1 50.65,76.65 IC3.6 52.17,77.05 R19.2
  BOTTOM w0.4: 52.7,71.62 R57.2 46.3,71.62 R56.2
  BOTTOM w0.5: 74,67.75 DP34.1
  BOTTOM w0.6: C15.2 C16.2 ; C15.2 73.95,37.55 74.25,37.85 C14.2 ; C15.2 73.45,39.1 73.95,39.6 v1(73.95,43.8) v1(73.95,45.6)
  BOTTOM w0.7: C11.2 53.3,75.6
  BOTTOM w0.8: C22.2 53.3,64.6 52.2,63.5 52.2,61.2 54.3,59.1 54.3,57.2 R18.1 R17.1 R16.1
  vias: v1(53.3,77.8) v1(53.3,76.3) v1(53.3,74.8) v1(53.3,73.3) v1(53.3,71.8) v1(53.3,70.3) v1(53.3,68.8) v1(53.3,67.3) v1(54.8,77.8) v1(54.8,76.3) v1(54.8,74.8) v1(56.3,77.8) v1(56.3,76.3) v1(56.3,74.8) v1(57.8,77.8) v1(57.8,76.3) v1(57.8,74.8) v1(59.3,76.3) v1(59.3,74.8) v1(60.8,76.3) v1(60.8,74.8) v1(60.8,73.3) v1(60.8,71.8) v1(60.8,70.3) v1(60.8,68.8) v1(60.8,67.3) v1(62.3,76.3) v1(62.3,74.8) v1(62.3,73.3) v1(62.3,71.8) v1(62.3,70.3) v1(62.3,68.8) v1(62.3,67.3) v1(62.3,65.8) v1(63.8,76.3) v1(63.8,74.8) v1(63.8,73.3) v1(63.8,71.8) v1(63.8,70.3) v1(63.8,68.8) v1(63.8,67.3) v1(63.8,65.8) v1(65.3,76.3) v1(65.3,74.8) v1(65.3,73.3) v1(65.3,71.8) v1(65.3,70.3) v1(65.3,68.8) v1(65.3,67.3) v1(65.3,65.8) v1(66.8,76.3) v1(66.8,74.8) v1(66.8,73.3) v1(66.8,71.8) v1(66.8,70.3) v1(66.8,68.8) v1(66.8,67.3) v1(66.8,65.8) v1(68.3,76.3) v1(68.3,74.8) v1(68.3,67.3) v1(68.3,65.8) v1(69.8,76.3) v1(71.3,76.3) v1(72.8,76.3)
VIN: length 68.8
  TOP w0.3: R38.2 v1(38.9,71.3)
  TOP w0.8: R39.1 v1(34.3,46.4)
  CONDUCTIVE4 w0.5: v1(38.9,71.3) 39,70.82 39,54.4 34.3,49.7 v1(34.3,46.4)
  CONDUCTIVE4 w1: v1(9.6,55.3) 11.4,53.5 16.7,53.5 19,51.2 19,48.3 22.7,44.6 32.5,44.6 v1(34.3,46.4)
  BOTTOM w0.3: R37.2 35.3,72.6 36.6,71.3 v1(38.9,71.3)
  vias: v1(5.1,77.8) v1(5.1,76.3) v1(5.1,74.8) v1(5.1,73.3) v1(5.1,71.8) v1(5.1,70.3) v1(5.1,68.8) v1(5.1,67.3) v1(5.1,65.8) v1(5.1,64.3) v1(5.1,62.8) v1(5.1,61.3) v1(5.1,59.8) v1(5.1,58.3) v1(5.1,56.8) v1(5.1,55.3) v1(6.6,77.8) v1(6.6,76.3) v1(6.6,74.8) v1(6.6,73.3) v1(6.6,71.8) v1(6.6,70.3) v1(6.6,68.8) v1(6.6,67.3) v1(6.6,65.8) v1(6.6,64.3) v1(6.6,62.8) v1(6.6,61.3) v1(6.6,59.8) v1(6.6,58.3) v1(6.6,56.8) v1(6.6,55.3) v1(8.1,77.8) v1(8.1,76.3) v1(8.1,74.8) v1(8.1,73.3) v1(8.1,71.8) v1(8.1,70.3) v1(8.1,68.8) v1(8.1,67.3) v1(8.1,65.8) v1(8.1,64.3) v1(8.1,62.8) v1(8.1,61.3) v1(8.1,59.8) v1(8.1,58.3) v1(8.1,56.8) v1(8.1,55.3) v1(9.6,77.8) v1(9.6,71.8) v1(9.6,70.3) v1(9.6,68.8) v1(9.6,67.3) v1(9.6,65.8) v1(9.6,64.3) v1(9.6,62.8) v1(9.6,61.3) v1(9.6,59.8) v1(9.6,58.3) v1(9.6,56.8)
$BN000001: length 1
  BOTTOM w0.3: Q9.D 34.1,68.53 R97.1
$BN000002: length 6.3
  BOTTOM w0.4: 44,71.6 44,70.2 44.4,69.8 R78.2 ; 44,71.6 45.42,71.6 ; 44,71.6 C48.2 43.48,71.62 42.5,70.65 D28.C
$BN000003: length 3.6
  TOP w0.3: C44.1 R50.2 ; C44.1 29.93,75.03 29.7,74.8 Q13.B ; C44.1 R75.1
$BN000004: length 2.5
  TOP w0.3: 30.4,76.72 R50.1 30.4,77.67 30,78.08 Q12.C
$BN000005: length 3.7
  BOTTOM w0.3: R79.2 35.6,66.6 35.97,66.97 DS1.E
AUX_2: length 18.3
  BOTTOM w1.5: 37.8,6.1 37.8,7.3 37.2,7.9 37.2,21.6 36.22,22.58 T2.3
CS: length 22
  BOTTOM w0.3: D1.C 19.35,50.6 23.5,54.75 23.5,65.88 R88.2 25.12,66.58 25.5,66.2 R45.2 R44.1
DC_IN: length 4
  TOP w0.5: DP31.1 18.35,69.75
  BOTTOM w0.5: DP31.1 18.35,69.75
  vias: v1(15.8,77.8) v1(15.8,71.8) v1(17.3,77.8) v1(17.3,76.3) v1(17.3,74.8) v1(17.3,73.3) v1(17.3,71.8) v1(18.8,77.8) v1(18.8,76.3) v1(18.8,74.8) v1(20.3,77.8) v1(20.3,76.3) v1(20.3,74.8) v1(21.8,77.8) v1(21.8,76.3) v1(21.8,74.8)
ENABLE: length 18.4
  BOTTOM w0.3: 30.88,70.4 25.6,70.4 20.6,65.4 CN3.1 ; 30.88,70.4 30.88,70.03 31.5,69.4 R40.1 ; 30.88,70.4 30.88,72.6
LGND: length 61.9
  TOP w0.3: C41.1 44.6,57.12
  TOP w0.4: C41.1 43.7,58.8
  TOP w0.5: 43.4,74.92 43.4,73.5 ; IC4.2 43.4,78.8 ; DP35.1 77.15,54.7
  TOP w0.6: IC4.5 42.31,78.7
  CONDUCTIVE4 w0.2: 78.85,42.65 73.55,47.95 69.25,47.95 56.6,60.6 44.58,60.6 v1(44.1,60.5)
  BOTTOM w0.3: v1(80.4,40.2) 80.17,39.98 79.17,39.98 ; 49.4,78.35 IC3.3 46.6,78.35
  BOTTOM w0.5: DP35.1 77.15,54.5
  BOTTOM w0.6: v1(45.2,66.1) 44.6,65.5 v1(43.7,65.5) 43.7,64.52 DS2.4 ; DS3.4 44.1,59.52 v1(44.1,60.5)
  vias: v1(42.3,78.7) v1(42.3,54.4) v1(42.4,50.2) v1(42.4,45.7) v1(42.8,80) v1(43,14.8) v1(43,9) v1(43,2) v1(43.2,73) v1(43.9,50.2) v1(43.9,48.7) v1(43.9,47.2) v1(43.9,45.7) v1(44.1,78.7) v1(45.2,55.7) v1(45.2,52.3) v1(45.4,50.2) v1(45.4,48.7) v1(45.4,47.2) v1(45.4,45.7) v1(47,80) v1(48,14.8) v1(48,9) v1(48,2) v1(48.4,79.2) v1(48.4,74.4) v1(51.7,74.4) v1(53,14.8) v1(53,9) v1(53,2) v1(54.4,80) v1(57.8,81.15) v1(58,9) v1(58,2) v1(62.8,81.15) v1(63,9) v1(63,2) v1(67.4,47.7) v1(67.6,21.7) v1(67.6,20.2) v1(67.6,18.7) v1(67.6,14.2) v1(67.8,81.15) v1(68,11.8) v1(68,9) v1(68,2) v1(68.1,35.2) v1(68.1,33.7) v1(68.6,51.6) v1(68.65,46.35) v1(69.1,23.2) v1(69.1,21.7) v1(69.1,20.2) v1(69.1,18.7) v1(69.1,17.2) v1(69.1,15.7) v1(69.1,14.2) v1(69.6,36.7) v1(69.6,35.2) v1(69.6,33.7) v1(70,50.9) v1(70,49.4) v1(70.6,24.7) v1(70.6,23.2) v1(70.6,21.7) v1(70.6,20.2) v1(70.6,18.7) v1(70.6,17.2) v1(70.6,15.7) v1(70.6,14.2) v1(71.1,34.8) v1(71.5,50.9) v1(71.5,49.4) v1(72.1,24.7) v1(72.1,23.2) v1(72.1,21.7) v1(72.1,20.2) v1(72.1,18.7) v1(72.1,17.2) v1(72.1,15.7) v1(72.1,14.2) v1(72.6,34.8) v1(72.8,81.15) v1(73,50.9) v1(73,49.4) v1(73,11.8) v1(73,9) v1(73,2) v1(73.6,30.7) v1(73.6,29.2) v1(73.6,27.7) v1(73.6,26.2) v1(73.6,24.7) v1(73.6,23.2) v1(73.6,21.7) v1(73.6,20.2) v1(73.6,18.7) v1(73.6,17.2) v1(73.6,15.7) v1(73.6,14.2) v1(74.1,34.8) v1(75.1,30.7) v1(75.1,29.2) v1(75.1,27.7) v1(75.1,26.2) v1(75.1,24.7) v1(75.1,23.2) v1(75.1,21.7) v1(75.1,20.2) v1(75.1,18.7) v1(75.1,17.2) v1(75.1,15.7) v1(75.1,14.2) v1(76,80) v1(76,76) v1(76,71) v1(76,63.6) v1(76,60.9) v1(76,56) v1(76,51) v1(76,47.2) v1(76.85,42.15) v1(78,38) v1(78,33) v1(78,28) v1(78,23) v1(78,18) v1(78,13) v1(78,9) v1(78,2) v1(78.6,51) v1(78.65,74.8) v1(78.65,70.6) v1(78.65,65.7) v1(78.65,60.95) v1(78.65,55.95) v1(80,80) v1(80,76) v1(81,73) v1(81,68) v1(81,63) v1(81,58) v1(81,53) v1(81,48) v1(81,43) v1(81,38) v1(81,33) v1(81,28) v1(81,23) v1(81,18) v1(81,13) v1(81,9) v1(81,2)
LM5046REF: length 41.4
  TOP w0.3: R49.2 32.62,74.08 v1(32.1,73.55) ; v1(32.1,73.55) 32.35,73.3 34.08,73.3 C31.2 34.17,74.67 IC5.1 ; v1(32.1,73.55) 31.5,74.15 R75.2 C44.2 ; IC1.7 30.93,64.41 v1(30.8,64.8) ; v1(37.3,69.4) 37.3,68.88 C36.2 ; Q13.E v1(28.98,76.9)
  CONDUCTIVE3 w0.2: v1(30.8,64.8) 32.3,64.8 33.85,66.35 34.75,66.35 37.3,68.9 v1(37.3,69.4) 37.1,69.84 37.1,70.4 35.8,71.7 33.95,71.7 v1(32.1,73.55) 30.85,74.8 30.85,75.03 v1(28.98,76.9)
  BOTTOM w0.3: 25.25,60.08 25.8,60.62 25.8,61.9 26.4,62.5 29.65,62.5 C45.2 30.8,63.65 v1(30.8,64.8)
  BOTTOM w0.6: DS1.C 37.3,68.23 v1(37.3,69.4)
LM5046VCC: length 106.1
  TOP w0.3: C29.2 29.8,54.15 29.8,54.6 30.27,55.08 IC1.21 ; v1(35,79.5) R47.2
  TOP w0.5: v1(29.9,52.9) 29.65,53.15 C29.2
  CONDUCTIVE4 w0.5: v1(29.9,52.9) 29.9,54.5 25.8,58.6 25.8,62.7 26.6,63.5 26.6,65.8 26.35,66.05 26.35,69.55 25.6,70.3 25.6,75 26.5,75.9 26.5,76.7 29.3,79.5 v1(35,79.5)
  BOTTOM w1: 16.4,10.7 24.4,10.7 25.2,11.5 25.2,22.45 19.75,27.9 17.5,27.9 15.73,29.68 15.73,41.18 17.54,43 24,43 28.85,47.85 D2.A 28.85,51.4 D9.A
  vias: v1(9.8,7.6) v1(9.8,6.1) v1(11.3,7.6) v1(11.3,6.1)
OUTB1: length 44.4
  CONDUCTIVE4 w0.2: v1(79.85,44.35) 77.75,44.35 73.75,48.35 69.45,48.35 56.5,61.3 v1(45.3,61.3)
  BOTTOM w0.3: R21.1 v1(79.85,44.35) ; R71.2 DP20.1 v1(45.3,61.3)
OUTB2: length 49.9
  CONDUCTIVE4 w0.2: v1(79.85,36.3) 79.55,36.6 79.55,41.35 73.35,47.55 69.05,47.55 56.7,59.9 v1(45.3,59.9)
  BOTTOM w0.3: v1(45.3,59.9) DP21.1 R73.2 ; v1(79.85,36.3) R22.1
PN: length 53.2
  TOP w0.3: 25.18,75.17 25.15,75.17 25.15,76.17 v1(25.3,76.7) ; 25,65.2 24.98,65.22 24.98,66.1 24.1,66.1 ; v1(35.75,78.4) 34.98,78.4 34.98,78.03 35.15,77.85 IC5.5 ; 37.8,59.52 R69.1 36.38,59.52 ; IC1.22 30.93,54.02 C29.1 ; C36.1 38.73,67.5 ; R48.1 v1(38.15,78.4)
  TOP w0.4: IC1.22 30.93,59.1 ; IC1.9 29.62,61.7
  TOP w0.5: v1(36.2,56) 36.27,55.92 36.27,54.38 C28.1 ; DP32.1 16.35,53.95 ; v1(30.95,52.2) C29.1
  TOP w0.6: T1.1 14.15,48.45 v1(14.6,48.9)
  BOTTOM w0.3: C35.1 26.85,64.22 C34.1 25.8,64.7 v1(25.7,65.1) ; Q9.S 33.33,69.72 33.4,69.8 R43.1 32.71,69.78 v1(32.3,69.7) 32.08,70.05 R41.1 ; v1(14.6,48.9) R1.1 19.38,49.77 24.1,54.5 24.1,64.8 v1(24.4,65.1)
  BOTTOM w0.5: DP32.1 16.35,53.6
  BOTTOM w0.6: v1(24.4,65.1) v1(25.7,65.1)
  vias: v1(1,80) v1(1,76) v1(1,71) v1(1,66) v1(1,61) v1(1,56) v1(1,51) v1(1,46) v1(1,36) v1(1,26) v1(1,21) v1(1,16) v1(1,11) v1(1,6) v1(1,2) v1(4,80) v1(4,49.6) v1(4,48.1) v1(4,6.7) v1(4,2) v1(5.8,4.1) v1(6.8,15.1) v1(6.8,13.6) v1(6.8,12.1) v1(7.3,6.7) v1(8.3,15.1) v1(8.3,13.6) v1(8.3,12.1) v1(9,80) v1(9,3.6) v1(9,2.1) v1(9.8,15.1) v1(9.8,13.6) v1(9.8,12.1) v1(10.5,3.6) v1(10.5,2.1) v1(11.3,13.6) v1(11.3,12.1) v1(12.8,15.1) v1(12.8,13.6) v1(12.8,12.1) v1(14,80) v1(14.1,2) v1(14.3,15.1) v1(14.3,13.6) v1(14.3,12.1) v1(15,68) v1(15,66.5) v1(15,65) v1(15,63.5) v1(15,62) v1(15,60.5) v1(15,59) v1(15,57.5) v1(15,56) v1(15.8,15.1) v1(15.8,13.6) v1(15.8,12.1) v1(16.5,66.5) v1(16.5,63.5) v1(16.5,62) v1(16.5,60.5) v1(16.5,59) v1(16.5,57.5) v1(16.5,56) v1(17.3,15.1) v1(17.3,13.6) v1(17.3,12.1) v1(18,60.5) v1(18,59) v1(18.3,80.55) v1(18.8,15.1) v1(18.8,13.6) v1(18.8,12.1) v1(19.5,59) v1(19.8,2) v1(20.3,13.6) v1(20.3,12.1) v1(21,59) v1(21.2,4.2) v1(21.8,13.6) v1(21.8,12.1) v1(22.5,59) v1(22.7,4.2) v1(23.3,12.1) v1(23.65,79.65) v1(24.2,4.2) v1(24.7,47.6) v1(24.9,61.7) v1(25.7,4.2) v1(26.5,73.4) v1(26.6,2) v1(26.7,61.7) v1(26.7,60.4) v1(26.7,59.1) v1(26.85,80.05) v1(27.3,68.3) v1(27.3,67) v1(28,73.4) v1(28,61.7) v1(28,60.4) v1(28,59.1) v1(28.7,13.6) v1(28.7,12.1) v1(29.3,61.7) v1(29.3,60.4) v1(29.3,59.1) v1(29.3,2) v1(29.5,73.4) v1(30.2,13.6) v1(30.2,12.1) v1(30.4,69.4) v1(30.6,61.7) v1(30.6,60.4) v1(30.6,59.1) v1(31.65,80.45) v1(31.7,13.6) v1(31.7,12.1) v1(31.8,6.1) v1(31.8,4.6) v1(31.9,61.7) v1(31.9,60.4) v1(31.9,59.1) v1(33.2,61.7) v1(33.2,60.4) v1(33.2,59.1) v1(33.3,6.1) v1(33.3,4.6) v1(34.5,61.7) v1(34.5,60.4) v1(34.5,59.1) v1(35.9,64.2) v1(37.1,65.8) v1(37.2,48.7) v1(37.2,47.2) v1(37.2,45.7) v1(37.3,76.4) v1(37.4,73.7) v1(37.5,50) v1(38.7,45.7) v1(38.75,80.4) v1(38.8,74.65) v1(38.8,50) v1(38.75,14.4) v1(38.75,9) v1(38.8,2)
SEC_1: length 2.5
  BOTTOM w1.7: T2.9 T2.8
  vias: v1(56,24.2) v1(56,22.7) v1(56,21.2) v1(56,19.7) v1(56,18.2) v1(56,16.7) v1(57.5,27.2) v1(57.5,25.7) v1(57.5,24.2) v1(57.5,22.7) v1(57.5,21.2) v1(57.5,19.7) v1(57.5,18.2) v1(57.5,16.7) v1(61.3,29.3) v1(61.3,28) v1(61.3,26.7) v1(61.3,22.8) v1(61.3,21.5) v1(61.3,20.2) v1(62.6,29.3) v1(62.6,28) v1(62.6,26.7) v1(62.6,22.8) v1(62.6,21.5) v1(62.6,20.2) v1(63.9,29.3) v1(63.9,28) v1(63.9,26.7) v1(63.9,22.8) v1(63.9,21.5) v1(63.9,20.2) v2(62.55,28) v2(62.55,21.5)
SEC_2: length 3.6
  BOTTOM w1.7: T2.6 T2.7
  vias: v1(47,57.2) v1(47,55.7) v1(47,54.2) v1(47,52.7) v1(47,51.2) v1(47,49.7) v1(47,48.2) v1(47,46.7) v1(48.5,58.7) v1(48.5,57.2) v1(48.5,55.7) v1(48.5,54.2) v1(48.5,52.7) v1(48.5,51.2) v1(48.5,49.7) v1(48.5,48.2) v1(48.5,46.7) v1(50,58.7) v1(50,57.2) v1(50,55.7) v1(50,54.2) v1(50,52.7) v1(50,51.2) v1(50,49.7) v1(50,48.2) v1(50,46.7) v1(51.5,58.7) v1(51.5,57.2) v1(51.5,55.7) v1(51.5,54.2) v1(51.5,52.7) v1(51.5,51.2) v1(51.5,49.7) v1(51.5,48.2) v1(51.5,46.7) v1(53,58.7) v1(53,57.2) v1(53,55.7) v1(53,54.2) v1(53,52.7) v1(53,51.2) v1(53,49.7) v1(53,48.2) v1(53,46.7)
SEC_3: length 2.5
  BOTTOM w1.7: T2.4 T2.5
  vias: v1(55.5,46.7) v1(55.5,45.2) v1(55.5,43.7) v1(55.5,42.2) v1(55.5,40.7) v1(55.5,39.2) v1(57,46.7) v1(57,45.2) v1(57,43.7) v1(57,42.2) v1(57,40.7) v1(57,39.2) v1(58,30.4) v1(61.3,42.3) v1(61.3,41) v1(61.3,39.7) v1(61.3,35.8) v1(61.3,34.5) v1(61.3,33.2) v1(62.6,42.3) v1(62.6,41) v1(62.6,39.7) v1(62.6,35.8) v1(62.6,34.5) v1(62.6,33.2) v1(63.9,42.3) v1(63.9,41) v1(63.9,39.7) v1(63.9,35.8) v1(63.9,34.5) v1(63.9,33.2) v2(62.55,41) v2(62.55,34.5)
SIG7: length 25.2
  TOP w0.3: IC1.26 33.52,55.17 v1(33.7,54.8)
  BOTTOM w0.7: v1(33.7,54.8) 33.9,54.8 35.6,53.1 35.6,50.5 DP1.1 25.3,40.2 D4.C 24.7,40.75 D3.A
SIG8: length 11.7
  TOP w0.3: IC1.25 32.88,56.65 32.92,56.6 32.92,54.42 v1(33.1,53.9)
  BOTTOM w0.4: C5.2 32.7,54.3 v1(33.1,53.9)
  BOTTOM w0.55: 33.85,53.4 33.35,53.9 v1(33.1,53.9)
  BOTTOM w0.7: 33.85,53.4 34.5,52.75 34.5,51.18 33.32,50 31.77,50 D2.C
SIG9: length 5
  BOTTOM w0.7: R3.2 R2.2 22,32.45 v1(22,32) R4.2
SIG12: length 5.2
  BOTTOM w0.7: R7.2 21.05,15.4 21.05,17 R6.2 R5.2 19.05,18.45 v1(19.1,18.5)
SIG14: length 8.5
  TOP w0.3: 28.32,57.52 28.32,55.68 v1(25.82,53.18)
  BOTTOM w0.4: C7.2 25.82,53.7 v1(25.82,53.18)
  BOTTOM w0.7: D9.C 25.82,52 v1(25.82,53.18)
SIG16: length 5.4
  BOTTOM w0.7: 11.72,15.4 11.85,15.4 11.85,17 R12.2 R11.2 9.65,18.45 v1(9.7,18.5)
SIG17: length 5
  BOTTOM w0.7: R9.2 R8.2 7.7,32.45 7.7,32 ; 7.7,32 v1(7.73,32) ; 7.7,32 R10.2
SIG18: length 51.2
  TOP w0.3: 28.4,52.3 28.8,52.7 28.8,54.45 29.62,55.28 IC1.20
  TOP w0.7: 28.4,52.3 26.9,50.8 DP4.1 v1(25.5,49.4)
  BOTTOM w0.7: D12.A D13.C 13.57,21.02 13.57,42.07 16.7,45.2 20.8,45.2 25,49.4 v1(25.5,49.4)
SIG22:
  vias: v1(4.4,35.55) v1(4.4,34.25) v1(5.2,34.9) v1(6,35.55) v1(6,34.25) v1(18.6,35.55) v1(18.6,34.25) v1(19.45,34.9) v1(20.3,35.55) v1(20.3,34.25)
SIG23: length 5
  TOP w0.3: v1(14.6,51.5) 13.95,52.15 T1.3
  BOTTOM w0.3: D1.A 16.45,50.62 R1.2 v1(14.6,51.5)
SIG25: length 1.9
  BOTTOM w0.3: Q9.G 33.33,68.25 33.17,68.25 33,68.08 R40.2
SIG27: length 11.1
  TOP w0.3: v1(32.5,71.2) 33.1,70.6 33.1,68.3 DP10.1 33,67.2 33.5,66.7 33.5,66.1 34.4,65.2 34.4,64.5 34.17,64.28 IC1.2
  BOTTOM w0.3: R42.1 R43.2 33.08,70.62 v1(32.5,71.2)
SIG28: length 1.9
  BOTTOM w0.3: R22.2 79.85,38.95 79.47,39.33 IC2.4
SIG29: length 2.7
  BOTTOM w0.3: IC2.2 79.67,40.62 79.95,40.9 79.95,42.58 R21.2
SIG41: length 31.1
  BOTTOM w0.8: D14.C 57.55,33.25 58.3,34 R36.2 C19.2 58.3,47.95 59.8,49.45 R17.2 ; R18.2 R17.2 ; R17.2 R16.2
  BOTTOM w1: D15.C D14.C
SIG43: length 3.8
  BOTTOM w0.3: IC3.4 51.05,78.35 51.58,78.88 C12.2 ; R20.2 C12.2 ; C12.2 R19.1
SIG49: length 9.8
  TOP w0.3: v1(31.85,65.95) 32.23,65.58 IC1.5 ; IC1.3 33.52,64.36 v1(33.6,64.9)
  BOTTOM w0.3: R91.1 R46.1 31.67,66.2 v1(31.85,65.95) 32.55,65.95 v1(33.6,64.9)
SIG52: length 7.1
  TOP w0.3: IC1.10 28.98,67.92 DP14.1 R89.2
SIG53: length 7.9
  TOP w0.3: R90.2 26.5,66.7 27.2,66 DP13.1 28.32,65.67 28.32,63.27
SIG54: length 20.6
  TOP w0.3: R66.1 38.12,60.38 DP18.1 v1(37.1,60.3) ; v1(32.5,52) 32.33,52.37 32.33,56.3 32.23,56.4 32.23,56.9
  TOP w0.4: IC1.24 32.23,56.9
  CONDUCTIVE4 w0.2: v1(32.5,52) 32.16,52.35 31.55,52.96 31.55,55.45 34.2,58.1 36.5,58.1 37.1,58.7 v1(37.1,60.3)
SIG55: length 20.2
  TOP w0.3: v1(37.1,55.2) DP17.1 37.92,56.02 R68.1 ; IC1.19 28.98,55.48 27.9,54.4 v1(27.9,53.1)
  CONDUCTIVE4 w0.2: v1(27.9,53.1) 27.9,51.86 29.19,50.58 32.48,50.58 v1(37.1,55.2)
SIG63: length 8.2
  TOP w0.3: IC1.28 34.83,56.88 35.2,56.5 35.2,54.65 35.05,54.5
  TOP w0.7: 35.05,54.5 C28.2 35.05,50.45 34.76,50.16 R39.2
SIG64: length 11.1
  TOP w0.3: IC1.4 32.88,66.22 DP11.1 32.1,67.5 31.5,68.1 v1(30.4,68.1)
  BOTTOM w0.3: R44.2 R46.2 R91.2 C30.2 30.1,68.4 v1(30.4,68.1)
SIG66: length 2.7
  TOP w0.3: IC1.12 27.68,64.38 v1(27.5,64.9)
  BOTTOM w0.3: v1(27.5,64.9) 27.93,64.47 C35.2
SIG67: length 19.6
  TOP w0.4: R55.2 v1(25.3,68.85) DP12.1 25.82,67.38 C33.2 26.7,65.22 26.7,64.5 27.02,64.17 27.02,63.27
  CONDUCTIVE3 w0.3: v1(25.3,68.85) 26.85,70.4 30.7,70.4 31.4,69.7 31.4,68.9 32.75,67.55 v1(33.9,67.55)
  BOTTOM w0.3: R97.2 34.02,67.67 v1(33.9,67.55)
SIG74: length 6.7
  TOP w0.3: v1(31.2,67.2) 31,67 31,65.7 31.58,65.12 IC1.6
  BOTTOM w0.3: 33.42,66.6 32.55,66.6 31.95,67.2 v1(31.2,67.2)
SIG75: length 2.8
  BOTTOM w0.7: R2.1 D3.C
SIG76: length 2.2
  BOTTOM w0.7: R3.1 D4.A
SIG77: length 3.1
  BOTTOM w0.7: R5.1 16.35,19.2 D5.C
SIG78: length 56.9
  TOP w0.3: 31.2,51.2 31.73,51.73 31.73,56.05 31.58,56.2 IC1.23
  TOP w0.7: 31.2,51.2 29.4,51.2 DP2.1 27.6,49.4 v1(27,49.4)
  BOTTOM w0.7: D5.A D6.C 21.65,24.35 19.25,26.75 16.85,26.75 14.57,29.02 14.57,41.66 17.11,44.2 23.4,44.2 27,47.8 v1(27,49.4)
SIG79: length 2.8
  BOTTOM w0.7: D6.A 23.55,17.2 R6.1
SIG80: length 2.8
  BOTTOM w0.7: D10.C R8.1
SIG81: length 30.5
  TOP w0.3: 24.8,54.4 26.2,54.4 27.68,55.88 IC1.17
  TOP w0.7: 24.8,54.4 24.2,54.4 22.7,52.9 DP3.1 v1(22.7,50)
  BOTTOM w0.7: D10.A 10.4,40.75 D11.C 11,42.4 15.8,47.2 19.9,47.2 v1(22.7,50)
SIG82: length 2.2
  BOTTOM w0.7: R9.1 D11.A
SIG83: length 3.1
  BOTTOM w0.7: R11.1 6.95,19.2 D12.C
SIG84: length 2.8
  BOTTOM w0.7: D13.A 14.35,17.2 R12.1
SIG85: length 4.5
  BOTTOM w0.7: 67.4,24.6 67.4,25.3 67.7,25.6 R33.2 R32.2 ; 67.4,24.6 v1(67.4,23.65) ; 67.4,24.6 R34.2
SIG86: length 15.9
  BOTTOM w0.35: 76.22,40.62 75.58,40.62 75.5,40.7 75.17,41.1
  BOTTOM w0.7: D17.C D16.A 69.8,45.95 70.55,46.7 DP5.1 74.4,46.7 75.17,45.92 75.17,41.1
SIG87: length 4.5
  BOTTOM w0.7: 67.45,37.6 67.45,38.35 67.75,38.65 67.75,39.45 ; 67.45,37.6 v1(67.45,36.7) ; 67.45,37.6 R28.2 ; R26.2 R27.2
SIG89: length 5.7
  BOTTOM w0.7: R26.1 R25.1 71.9,44.8 D16.C
SIG90: length 3
  BOTTOM w0.7: v1(67.45,43.2) 67.7,42.95 R24.2 R25.2
SIG91: length 5.6
  BOTTOM w0.7: R27.1 R24.1 65,44.9 D17.A
SIG92: length 15.1
  BOTTOM w0.35: 76.4,38.2 76.22,38.7 76.22,39.33
  BOTTOM w0.7: D19.C D18.A 69.8,32.55 70.45,33.2 74.2,33.2 DP6.1 76.4,35.4 76.4,38.2
SIG93: length 3
  BOTTOM w0.7: R31.2 R30.2 67.7,29.95 v1(67.45,30.2)
SIG94: length 5.6
  BOTTOM w0.7: R33.1 R30.1 65,31.9 D19.A
SIG95: length 5.7
  BOTTOM w0.7: R32.1 R31.1 71.9,31.8 D18.C
SIG97: length 2.3
  TOP w0.3: v1(36.2,61.8) R66.2
  BOTTOM w0.3: v1(36.2,61.8) 37.22,61.8 DS2.1
SIG98: length 1.6
  BOTTOM w0.3: DS2.3 37.23,64.47 36.6,65.1 R67.2
SIG99: length 2.3
  TOP w0.3: R68.2 v1(36.2,57.3)
  BOTTOM w0.3: v1(36.2,57.3) 36.64,56.96 37.07,56.53 DS3.1
SIG100: length 2.2
  TOP w0.3: v1(36.2,58.8) 36.74,58.67 R69.2
  BOTTOM w0.6: v1(36.2,58.8) 36.47,59.07 DS3.3
SIG106: length 3.9
  TOP w0.3: v1(42.8,60.5) 42.8,61.42 C40.2 42.88,62.55 R70.1
  BOTTOM w0.6: v1(42.8,60.5) 43.4,61.1 43.4,61.68 DS2.6
SIG107: length 2
  BOTTOM w0.3: DS2.5 44.1,63.2 45.02,64.12 R71.1
SIG108: length 3
  TOP w0.4: v1(43.7,55.5) C41.2 R72.1
  BOTTOM w0.6: v1(43.7,55.5) 43.7,56.48 DS3.6
SIG109: length 2
  BOTTOM w0.3: R73.1 44.83,57.08 44.1,57.8 DS3.5
SIG112: length 3.3
  TOP w0.3: v1(25,63.9) 25.2,64.1 26.1,64.1 26.38,63.83 IC1.14
  BOTTOM w0.3: C34.2 25.2,63.38 25,63.58 v1(25,63.9)
SIG122: length 21
  TOP w0.3: v1(44.8,70.65) 44.5,70.95 DP19.1 44.5,74.91 44.49,74.92 IC4.3 44.74,74.88 R58.1 C37.2 47.23,74.88 47.52,75.17 47.52,76.53 47.28,76.78 C46.2
  BOTTOM w0.4: v1(44.8,70.65) 46.98,70.65 47.1,70.78 R57.1 48.05,68.55 46.67,67.17 R77.1 45.15,67.17 44.94,66.97 DS1.CA
SIG124: length 2.2
  TOP w0.3: C37.1 R58.2 C38.2
SIG126: length 1
  TOP w0.3: R52.2 R51.1
SIG127: length 7
  TOP w0.3: IC1.8 30.27,64.22 29.6,64.9 29.6,68.8 DP15.1 R51.2
SIG129: length 4.5
  BOTTOM w0.4: R78.1 45.85,69.78 R77.2 45.25,68.03 45.04,68.23 DS1.A
SIG130: length 1.1
  TOP w0.3: R60.1 R61.2
SIG131: length 1.1
  TOP w0.3: R62.2 C39.2
SIG132: length 2
  TOP w0.3: R59.1 C39.1 R60.2
SIG133: length 3.6
  TOP w0.3: IC1.15 25.24,57.52 v1(24.97,57.26)
  BOTTOM w0.3: v1(24.97,57.26) 25.27,57.56 R65.2 25.25,58.23 R64.1
SIG145: length 45.5
  TOP w0.3: IC1.27 34.17,56.54 v1(34.3,56)
  CONDUCTIVE3 w0.7: v1(17.9,30.7) 15.8,32.8 15.8,37.7 23.7,45.6 28.8,45.6 35.3,52.1 35.3,55 v1(34.3,56)
  BOTTOM w0.4: v1(34.3,56) 33.23,56 32.7,55.48
  BOTTOM w0.7: v1(17.9,30.7) 18.5,30.1 22,30.1 R4.1
  vias: v1(17,23.4) v1(17,22.15) v1(17.8,22.75) v1(18.6,23.4) v1(18.6,22.15)
SIG148: length 41.5
  TOP w0.3: v1(25.85,55.45) 26.19,55.69 27.02,56.53 27.02,57.52
  CONDUCTIVE3 w0.7: v1(5.3,30.7) 5.8,30.2 9,30.2 10.75,31.95 10.75,40.85 25.36,55.45 v1(25.85,55.45)
  BOTTOM w0.4: C7.1 26.26,55.42 v1(25.85,55.45)
  BOTTOM w0.7: R10.1 7.7,28.6
  vias: v1(5.6,28.6) v1(5.6,27.1) v1(7.1,28.6) v1(7.1,27.1) v1(7.8,23.45) v1(7.8,22.15) v1(8.6,28.6) v1(8.6,27.1) v1(8.6,22.8) v1(9.4,23.45) v1(9.4,22.15) v1(10.1,28.6) v1(10.1,27.1)
SIG151: length 3.6
  TOP w0.4: Q11.D 25.3,74.33 R55.1
SIG153: length 3.3
  TOP w0.25: Q11.G 26.02,75.17 26.3,75.45 Q13.C
  TOP w0.3: R74.2 26.6,76.58 27.02,76.15 Q13.C
SIG155: length 1.3
  TOP w0.3: C32.2 34.12,77.88 34.2,77.8 IC5.6
SIG156: length 2.6
  TOP w0.3: R47.1 36.52,77.53 IC5.4
SIG158: length 4.6
  TOP w0.3: R80.2 DP9.1
  TOP w0.4: IC1.1 34.83,64 35.08,64.25 C47.2 35.08,66.42 DP9.1
SIG161: length 3.4
  BOTTOM w0.3: Q10.C 17.3,3.08 R15.2
SIG162:
  vias: v1(34.8,6.1) v1(34.8,4.6) v1(36.3,6.1) v1(36.3,4.6)
SIG164: length 5
  BOTTOM w0.3: 18.62,2.8 18.52,2.7 ; 18.62,2.8 D21.C ; 18.62,2.8 18.8,2.98 Q10.B
SIG170: length 4.2
  TOP w0.3: R49.1 D29.A 34.75,75.88 35.15,75.47 IC5.2
SIG172: length 10.3
  TOP w0.3: R74.1 26.6,78.4 27.25,79.05 29.2,79.05 29.65,79.5 Q12.B 31.1,78.58 R87.2 32.77,78.58 C43.2 D29.C
SIG173: length 1
  TOP w0.3: R53.2 R89.1
SIG174: length 1
  TOP w0.3: R90.1 R54.2
SIG176: length 4.4
  TOP w0.3: R80.1 34.9,69.3 v1(35.5,69.9) 35.5,70.33 R38.1
  BOTTOM w0.3: v1(35.5,69.9) 35.11,69.78 R42.2
SIG178: length 6.2
  TOP w0.3: IC4.4 44.84,77.62 C38.1 C46.1 47.4,77.62 47.55,77.47 R63.2 R62.1 R61.1

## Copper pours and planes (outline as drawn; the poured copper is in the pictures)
12VOUT on TOP: 62.38,64.5 62.31,64.52 62.24,64.56 59.96,66.84 59.89,66.88 59.82,66.9 53.1,66.9 52.89,66.99 52.8,67.2 52.8,77.82 52.82,77.89 52.86,77.96 53.14,78.24 53.21,78.28 53.28,78.3 73.42,78.3 73.49,78.28 73.56,78.24 74.44,77.36 74.48,77.29 74.5,77.22 74.5,72.05 74.5,65.63 74.49,65.58 74.44,65.49 73.49,64.54 73.45,64.51 73.39,64.5 73.26,64.52 73.2,64.52 72.8,64.52 72.74,64.52 72.64,64.5
12VOUT on BOTTOM: 53,64.1 52.9,64.13 52.83,64.2 52.8,64.3 52.8,70.97 52.77,71.07 52.74,71.11 52.31,71.54 52.27,71.64 52.31,71.75 52.49,71.93 52.52,71.95 52.62,72.03 52.7,72.13 52.74,72.18 52.79,72.27 52.8,72.32 52.8,74.9 52.36,75.34 52.33,75.38 52.3,75.48 52.3,75.72 52.31,75.77 52.36,75.86 52.74,76.24 52.79,76.33 52.8,76.38 52.8,77.44 52.81,77.48 52.88,77.64 52.9,77.78 52.9,77.93 52.91,77.99 52.94,78.04 53.09,78.19 53.13,78.22 53.19,78.23 53.5,78.23 53.62,78.24 53.76,78.3 53.79,78.3 54.6,78.3 58.47,78.3 58.52,78.29 58.61,78.24 59.04,77.81 59.13,77.76 59.18,77.75 74.3,77.75 74.4,77.72 74.47,77.65 74.5,77.55 74.5,76.2 74.5,72 74.5,64.88 74.49,64.83 74.44,64.74 73.86,64.16 73.82,64.13 73.72,64.1
12VOUT on CONDUCTIVE3: 64.56,64.44 64.47,64.49 64.42,64.5 62.34,64.5 62.3,64.51 62.27,64.53 59.89,66.88 59.82,66.9 53.1,66.9 52.89,66.99 52.8,67.2 52.8,77.82 52.82,77.89 52.86,77.96 53.14,78.24 53.21,78.28 53.28,78.3 73.42,78.3 73.47,78.29 73.56,78.24 74.44,77.36 74.47,77.32 74.5,77.22 74.5,64.7 74.47,64.6 74.4,64.53 74.3,64.5 66.9,64.5 65.84,63.44 65.75,63.39 65.65,63.39 65.56,63.44
12VOUT on CONDUCTIVE4: 62.38,64.5 62.33,64.51 62.24,64.56 59.89,66.88 59.82,66.9 53.1,66.9 52.95,66.94 52.84,67.05 52.8,67.2 52.8,77.82 52.81,77.87 52.86,77.96 53.14,78.24 53.18,78.27 53.28,78.3 73.42,78.3 73.47,78.29 73.56,78.24 74.44,77.36 74.47,77.32 74.5,77.22 74.5,64.7 74.47,64.6 74.4,64.53 74.3,64.5
VIN on TOP: 7.76,51.6 7.65,51.64 7.61,51.75 7.61,52.73 7.21,53.69 6.25,54.09 5.1,54.09 5.04,54.1 5,54.13 4.66,54.47 4.62,54.53 4.6,54.61 4.6,77.72 4.61,77.77 4.66,77.86 4.94,78.14 4.98,78.17 5.08,78.2 8.9,78.2 10.12,78.2 10.17,78.19 10.26,78.14 10.64,77.76 10.67,77.72 10.7,77.62 10.7,70.28 10.73,70.18 10.76,70.14 11.34,69.56 11.37,69.52 11.4,69.42 11.4,54.06 11.38,53.99 10.79,53.43 10.6,52.73 10.6,51.75 10.55,51.64 10.45,51.6
VIN on BOTTOM: 5.1,54.09 5.04,54.1 5,54.13 4.66,54.47 4.63,54.51 4.6,54.61 4.6,77.72 4.61,77.77 4.66,77.86 4.94,78.14 4.98,78.17 5.08,78.2 9.97,78.2 10.02,78.19 10.11,78.14 10.39,77.86 10.42,77.82 10.45,77.72 10.45,76.6 10.45,73.1 10.45,54.68 10.43,54.61 10.39,54.54 9.99,54.14 9.93,54.1 9.85,54.09
VIN on CONDUCTIVE3: 5.1,54.09 5.04,54.1 5,54.13 4.66,54.47 4.62,54.53 4.6,54.61 4.6,77.72 4.61,77.77 4.66,77.86 4.94,78.14 4.98,78.17 5.08,78.2 9.97,78.2 10.02,78.19 10.11,78.14 10.39,77.86 10.42,77.82 10.45,77.72 10.45,54.68 10.43,54.61 10.39,54.54 9.99,54.14 9.93,54.1 9.85,54.09
VIN on CONDUCTIVE4: 5.1,54.09 5.04,54.1 5,54.13 4.66,54.47 4.62,54.53 4.6,54.61 4.6,77.72 4.62,77.79 4.66,77.86 4.94,78.14 4.98,78.17 5.08,78.2 9.97,78.2 10.02,78.19 10.11,78.14 10.39,77.86 10.42,77.82 10.45,77.72 10.45,76.6 10.45,73.1 10.45,54.28 10.39,54.14 10.25,54.09
AUX_1 on BOTTOM: 30.4,7.8 30.25,7.84 30.14,7.95 30.1,8.1 30.1,9.04 30.11,9.1 30.14,9.14 30.54,9.54 30.58,9.57 30.68,9.6 33.48,9.6 33.63,9.64 33.69,9.69 34.11,10.11 34.19,10.25 34.2,10.32 34.2,20.1 34.24,20.25 34.35,20.36 34.5,20.4 35.5,20.4 35.65,20.36 35.76,20.25 35.8,20.1 35.8,8.66 35.79,8.6 35.76,8.56 35.09,7.89 35.03,7.84 34.88,7.8
AUX_2 on BOTTOM: 30.68,1.2 30.63,1.21 30.54,1.26 30.16,1.64 30.13,1.68 30.1,1.78 30.1,2.5 30.14,2.65 30.25,2.76 30.4,2.8 36.42,2.8 36.52,2.83 36.56,2.86 36.99,3.29 37.04,3.38 37.05,3.43 37.05,6.4 37.09,6.55 37.2,6.66 37.35,6.7 38.25,6.7 38.4,6.66 38.51,6.55 38.55,6.4 38.55,2.73 38.54,2.68 38.49,2.59 37.14,1.24 37.1,1.21 37.04,1.2
DC_IN on TOP: 18.93,68.8 18.86,68.81 18.79,68.86 18.19,69.46 18.16,69.5 18.15,69.56 18.15,69.59 18.04,70.14 17.73,70.61 17.41,70.93 16.91,71.27 16.32,71.4 16.28,71.4 15.25,71.4 15.19,71.41 15.14,71.44 14.76,71.83 14.73,71.87 14.7,71.97 14.7,77.62 14.71,77.67 14.76,77.76 15.14,78.14 15.18,78.17 15.28,78.2 20.5,78.2 21.92,78.2 21.97,78.19 22.06,78.14 22.96,77.24 22.99,77.2 23,77.14 23,69.96 22.99,69.9 22.96,69.86 21.94,68.84 21.9,68.81 21.84,68.8
DC_IN on BOTTOM: 18.93,68.8 18.88,68.81 18.79,68.86 18.19,69.46 18.16,69.5 18.15,69.56 18.15,69.59 18.04,70.14 17.73,70.61 17.41,70.93 16.89,71.28 16.28,71.4 15.38,71.4 15.31,71.42 15.24,71.46 14.86,71.84 14.82,71.91 14.8,71.98 14.8,77.52 14.82,77.59 14.86,77.66 15.34,78.14 15.38,78.17 15.48,78.2 21.92,78.2 21.97,78.19 22.06,78.14 22.94,77.26 22.97,77.22 23,77.12 23,69.98 22.99,69.93 22.94,69.84 21.94,68.84 21.9,68.81 21.84,68.8
